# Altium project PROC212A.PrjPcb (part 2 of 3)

## Sheet PROC212A_ANALOG_JTAG_MUX, CAN & SOP_CTRL.SchDoc: JTAG_ANALOG_MUX, CAN & SOP_CTRL
size 431 x 279 mm; Date: Not shown in title block; ApprovedBy: Not shown in title block; CheckedBy: Not shown in title block; Author: Not shown in title block; CompanyName: Not shown in title block; DrawnBy: Mistral; Engineer: Not shown in title block; Organization: Not shown in title block; Address1: Not shown in title block; Address2: Not shown in title block; Address3: Not shown in title block; Address4: Not shown in title block; DocumentNumber: 9; Revision: Use project parameter SCH_Rev; SheetNumber: 9; SheetTotal: 15; PageSetup: Record=PageOptions¦CenterHorizontal=True¦CenterVertical=True¦PrintScale=1.00¦XCorrection=1.00¦YCorrection=1.00¦PrintKind=0¦BorderSize=5000000¦LeftOffset=0¦BottomOffset=0¦Orientation=2¦PaperLength=1000¦PaperWidth=1000¦Scale=100¦PaperSource=15¦PrintQuality=600¦MediaType=1¦DitherType=10¦PaperKind=Letter¦PrintScaleMode=1
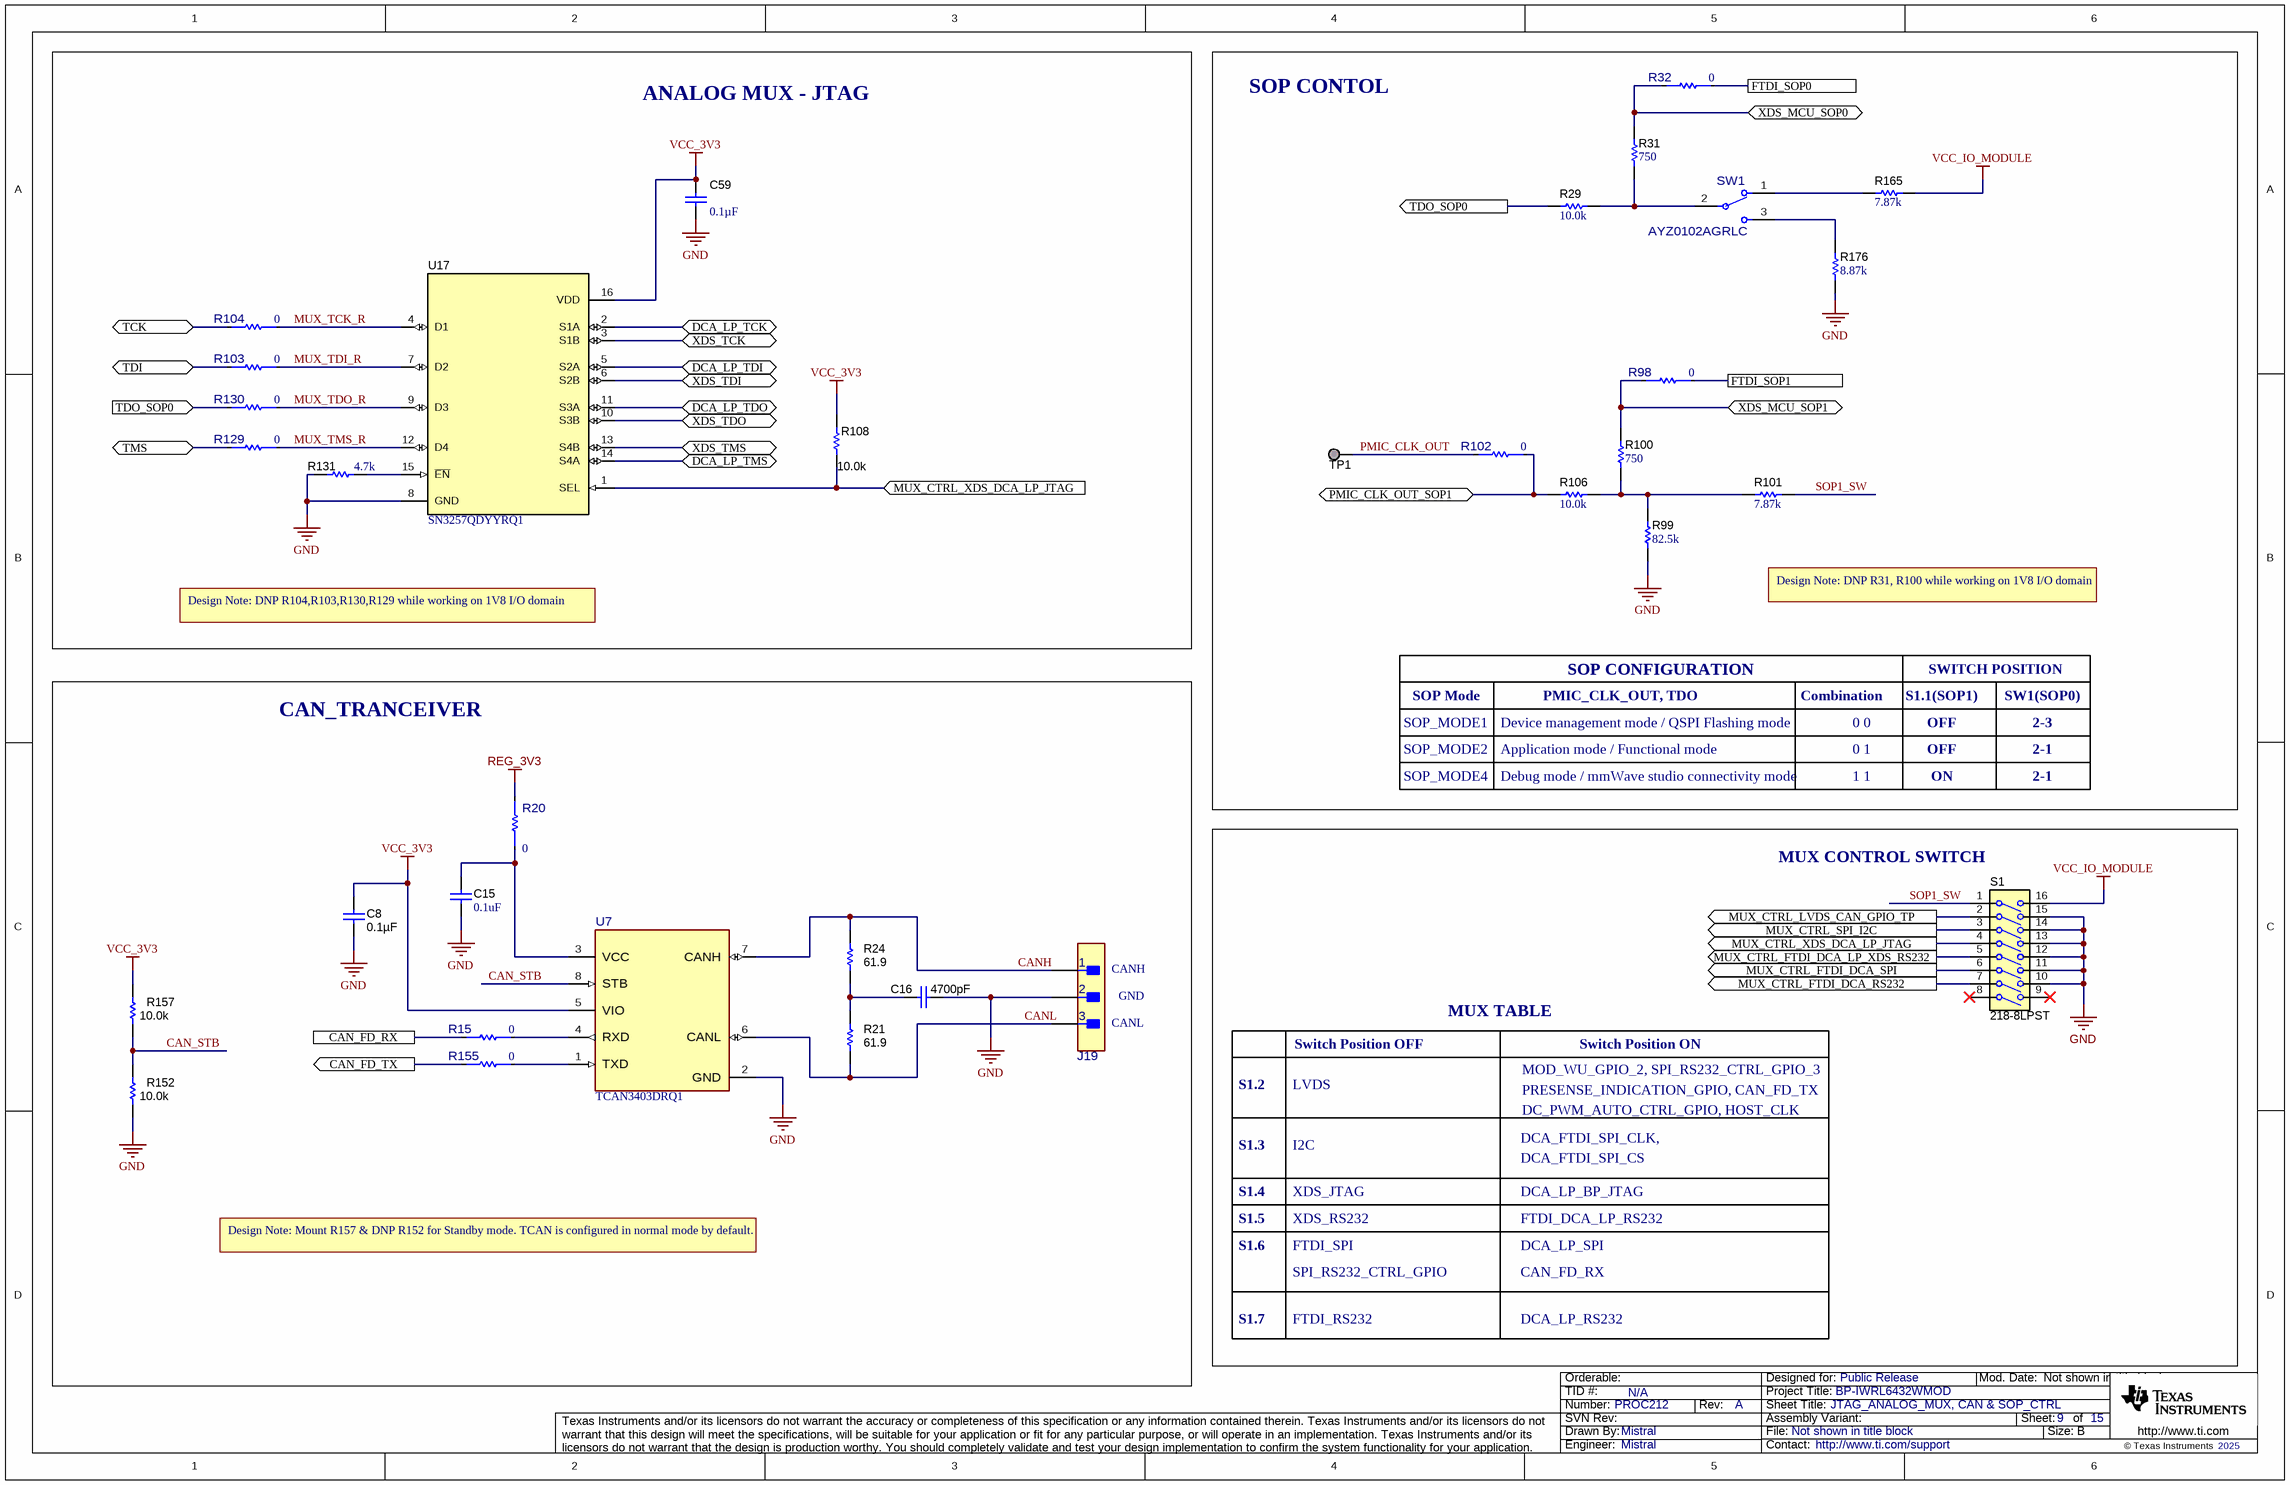
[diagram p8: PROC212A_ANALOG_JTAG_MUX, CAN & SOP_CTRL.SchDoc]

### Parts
C8  ValueDisplayed: 0.1µF  [0402L]  (hidden comment: C0402C104K8RACTU)
C15  ValueDisplayed: 0.1uF  [0402]  (hidden comment: GCM155R71H104KE02D)
C16  ValueDisplayed: 4700pF  [0402L]  (hidden comment: GCM155R71H472KA37D)
C59  ValueDisplayed: 0.1µF  [0402]  (hidden comment: C0402C104K8RACTU)
J19  M50-3930342  [FP-M50-3930342_HDR3-MFG]  (value not drawn)
R15  value 0  [FP-ERJ-2GE0R00X_0402-MFG]  (hidden comment: ERJ-2GE0R00X)
R20  value 0  [FP-ERJ-2GE0R00X_0402-MFG]  (hidden comment: ERJ-2GE0R00X)
R21  ValueDisplayed: 61.9  [0402L]  (hidden comment: CRCW040261R9FKED)
R24  ValueDisplayed: 61.9  [0402L]  (hidden comment: CRCW040261R9FKED)
R29  ValueDisplayed: 10.0k  [0402L]  (hidden comment: CRCW040210K0FKED)
R31  ValueDisplayed: 750  [0402L]  (hidden comment: CRCW0402750RFKED)
R32  value 0  [FP-ERJ-2GE0R00X_0402-MFG]  (hidden comment: ERJ-2GE0R00X)
R98  value 0  [FP-ERJ-2GE0R00X_0402-MFG]  (hidden comment: ERJ-2GE0R00X)
R99  ValueDisplayed: 82.5k  [0402L]  (hidden comment: CRCW040282K5FKED)
R100  ValueDisplayed: 750  [0402L]  (hidden comment: CRCW0402750RFKED)
R101  ValueDisplayed: 7.87k  [0402L]  (hidden comment: CRCW04027K87FKED)
R102  value 0  [FP-ERJ-2GE0R00X_0402-MFG]  (hidden comment: ERJ-2GE0R00X)
R103  value 0  [FP-ERJ-2GE0R00X_0402-MFG]  (hidden comment: ERJ-2GE0R00X)
R104  value 0  [FP-ERJ-2GE0R00X_0402-MFG]  (hidden comment: ERJ-2GE0R00X)
R106  ValueDisplayed: 10.0k  [0402L]  (hidden comment: CRCW040210K0FKED)
R108  ValueDisplayed: 10.0k  [0402L]  (hidden comment: CRCW040210K0FKED)
R129  value 0  [FP-ERJ-2GE0R00X_0402-MFG]  (hidden comment: ERJ-2GE0R00X)
R130  value 0  [FP-ERJ-2GE0R00X_0402-MFG]  (hidden comment: ERJ-2GE0R00X)
R131  ValueDisplayed: 4.7k  [0402]  (hidden comment: CRCW04024K70JNED)
R152  ValueDisplayed: 10.0k  [0402L]  (hidden comment: CRCW040210K0FKED)
R155  value 0  [FP-ERJ-2GE0R00X_0402-MFG]  (hidden comment: ERJ-2GE0R00X)
R157  ValueDisplayed: 10.0k  [0402L]  (hidden comment: CRCW040210K0FKED)
R165  ValueDisplayed: 7.87k  [0402L]  (hidden comment: CRCW04027K87FKED)
R176  ValueDisplayed: 8.87k  [0402]  (hidden comment: CRCW04028K87FKED)
S1  218-8LPST  [SW_218-8LP]
SW1  AYZ0102AGRLC  [FP-AYZ0102AGRLC_SMT_SW_7MM2_5MM3-MFG]
TP1  TESTPOINT  [TP_25MIL-SMT]  (value not drawn)  (no BOM)
U7  TCAN3403DRQ1  [D0008B-MFG]
U17  SN3257QDYYRQ1  [DYY0016A]

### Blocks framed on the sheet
ANALOG MUX - JTAG: C59 R103 R104 R108 R129-R131 U17
SOP CONTOL: R29 R31 R32 R98-R102 R106 R165 R176 SW1 TP1
CAN_TRANCEIVER: C8 C15 C16 J19 R15 R20 R21 R24 R152 R155 R157 U7

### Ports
CAN_FD_RX, CAN_FD_TX (out), DCA_LP_TCK (bidir), DCA_LP_TDI (bidir), DCA_LP_TDO (bidir), DCA_LP_TMS (bidir), FTDI_SOP0, FTDI_SOP1, MUX_CTRL_FTDI_DCA_LP_XDS_RS232 (out), MUX_CTRL_FTDI_DCA_RS232 (out), MUX_CTRL_FTDI_DCA_SPI (out), MUX_CTRL_LVDS_CAN_GPIO_TP (out), MUX_CTRL_SPI_I2C (out), MUX_CTRL_XDS_DCA_LP_JTAG (in), MUX_CTRL_XDS_DCA_LP_JTAG (out), PMIC_CLK_OUT_SOP1 (bidir), TCK (bidir), TDI (bidir), TDO_SOP0 (in), TDO_SOP0 (out), TMS (bidir), XDS_MCU_SOP0 (bidir), XDS_MCU_SOP1 (bidir), XDS_TCK (bidir), XDS_TDI (bidir), XDS_TDO (bidir), XDS_TMS (bidir)

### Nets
GND: C8.1 C15.1 C16.1 C59.2 J19.2 R99.1 R131.1 R152.1 R176.1 S1.10(7A) S1.11(6A) S1.12(5A) S1.13(4A) S1.14(3A) S1.15(2A) U7.2(GND) U17.8(GND)
REG_3V3: R20.2
VCC_3V3: C8.2 C59.1 R108.2 R157.2 U7.5(VIO) U17.16(VDD)
VCC_IO_MODULE: R165.2 S1.16(1A)
CAN_FD_RX: R15.2 ; port CAN_FD_RX
CAN_FD_TX: R155.2 ; port CAN_FD_TX
CAN_STB: R152.2 R157.1 U7.8(STB)
CANH: J19.1 R24.2 U7.7(CANH)
CANL: J19.3 R21.1 U7.6(CANL)
DCA_LP_TCK: U17.2(S1A) ; port DCA_LP_TCK
DCA_LP_TDI: U17.5(S2A) ; port DCA_LP_TDI
DCA_LP_TDO: U17.11(S3A) ; port DCA_LP_TDO
DCA_LP_TMS: U17.14(S4A) ; port DCA_LP_TMS
FTDI_SOP0: R32.1 ; port FTDI_SOP0
FTDI_SOP1: R98.1 ; port FTDI_SOP1
MUX_CTRL_FTDI_DCA_LP_XDS_RS232: S1.5 ; port MUX_CTRL_FTDI_DCA_LP_XDS_RS232
MUX_CTRL_FTDI_DCA_RS232: S1.7 ; port MUX_CTRL_FTDI_DCA_RS232
MUX_CTRL_FTDI_DCA_SPI: S1.6 ; port MUX_CTRL_FTDI_DCA_SPI
MUX_CTRL_LVDS_CAN_GPIO_TP: S1.2 ; port MUX_CTRL_LVDS_CAN_GPIO_TP
MUX_CTRL_SPI_I2C: S1.3 ; port MUX_CTRL_SPI_I2C
MUX_CTRL_XDS_DCA_LP_JTAG: R108.1 S1.4 U17.1(SEL) ; port MUX_CTRL_XDS_DCA_LP_JTAG
MUX_TCK_R: R104.1 U17.4(D1)
MUX_TDI_R: R103.1 U17.7(D2)
MUX_TDO_R: R130.1 U17.9(D3)
MUX_TMS_R: R129.1 U17.12(D4)
PMIC_CLK_OUT: R102.2 TP1.1
PMIC_CLK_OUT_SOP1: R102.1 R106.1 ; port PMIC_CLK_OUT_SOP1
SOP1_SW: R101.2 S1.1
TCK: R104.2 ; port TCK
TDI: R103.2 ; port TDI
TDO_SOP0: R29.1 R130.2 ; port TDO_SOP0
TMS: R129.2 ; port TMS
XDS_MCU_SOP0: R31.1 R32.2 ; port XDS_MCU_SOP0
XDS_MCU_SOP1: R98.2 R100.1 ; port XDS_MCU_SOP1
XDS_TCK: U17.3(S1B) ; port XDS_TCK
XDS_TDI: U17.6(S2B) ; port XDS_TDI
XDS_TDO: U17.10(S3B) ; port XDS_TDO
XDS_TMS: U17.13(S4B) ; port XDS_TMS
NetC15_2: C15.2 R20.1 U7.3(VCC)
NetC16_2: C16.2 R21.2 R24.1
NetR15_1: R15.1 U7.4(RXD)
NetR29_2: R29.2 R31.2 SW1.2(C)
NetR99_2: R99.2 R100.2 R101.1 R106.2
NetR131_2: R131.2 U17.15(~{EN})
NetR155_1: R155.1 U7.1(TXD)
NetR165_1: R165.1 SW1.1
NetR176_2: R176.2 SW1.3

Not connected (* = marked no-connect by the designer): S1 8* 9(8A)*

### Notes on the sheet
- Design Note: DNP R104,R103,R130,R129 while working on 1V8 I/O domain
- Design Note: DNP R31, R100 while working on 1V8 I/O domain
- SOP Mode
- PMIC_CLK_OUT, TDO
- SOP CONFIGURATION
- Combination
- S1.1(SOP1)
- SWITCH POSITION
- SW1(SOP0)
- SOP_MODE1
- SOP_MODE2
- Device management mode / QSPI Flashing mode
- Application mode / Functional mode
- 0 0
- 0 1
- OFF
- 2-1
- 2-3
- SOP_MODE4
- Debug mode / mmWave studio connectivity mode
- 1 1
- ON
- (near S1) MUX CONTROL SWITCH
- (near J19) CANH
- (near J19) CANL
- (near J19) GND
- MUX TABLE
- S1.2
- LVDS
- Switch Position OFF
- MOD_WU_GPIO_2, SPI_RS232_CTRL_GPIO_3
- PRESENSE_INDICATION_GPIO, CAN_FD_TX
- DC_PWM_AUTO_CTRL_GPIO, HOST_CLK
- Switch Position ON
- S1.3
- I2C
- DCA_FTDI_SPI_CLK,
- DCA_FTDI_SPI_CS
- Design Note: Mount R157 & DNP R152 for Standby mode. TCAN is configured in normal mode by default.
- S1.4
- S1.5
- S1.6
- XDS_RS232
- XDS_JTAG
- FTDI_SPI
- FTDI_DCA_LP_RS232
- DCA_LP_BP_JTAG
- DCA_LP_SPI
- SPI_RS232_CTRL_GPIO
- CAN_FD_RX
- S1.7
- FTDI_RS232
- DCA_LP_RS232

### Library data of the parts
C8 = CMP-0078241-1: CAP, CERM, 0.1 µF, 10 V,+/- 10%, X7R, 0402; Manufacturer: Kemet; TaMin_C: -55°C; Polarized: N; SizeAreaWB_mm2: 3; U/M: EA; Value: 0.1uF; TaMax_C: 125°C; SizeZ_mm: 0.6; SizeX_mm: 1; SizeY_mm: 0.5; Cap_Case: 0402; Value2: 10V; CompType: Capacitor; Cap_F: 100nF; AEC Category: Q200
C15 = CMP-0006356-2: CAP, CERM, 0.1 uF, 50 V, +/- 10%, X7R, AEC-Q200 Grade 1, 0402; Manufacturer: MuRata; TaMin_C: -55°C; Polarized: N; SizeAreaWB_mm2: 3; U/M: EA; Value: 0.1uF; TaMax_C: 125°C; SizeZ_mm: 0.6; SizeX_mm: 1; SizeY_mm: 0.5; Value2: 50V; AEC Qualified: Y; Cap_F: 100nF; AEC Category: Q200; Value1: Unknown
C16 = CMP-0006361-2: CAP, CERM, 4700 pF, 50 V, +/- 10%, X7R, AEC-Q200 Grade 1, 0402; Manufacturer: MuRata; TaMin_C: -55°C; Polarized: N; SizeAreaWB_mm2: 3; Value1: Unknown; U/M: EA; Value: 4700pF; TaMax_C: 125°C; SizeZ_mm: 0.6; SizeX_mm: 1; SizeY_mm: 0.5; Cap_Case: 0402; Value2: 50V; AEC Qualified: Y; Cap_F: 4.7nF; AEC Category: Q200
C59 = CMP-0078241-1: CAP, CERM, 0.1 µF, 10 V,+/- 10%, X7R, 0402; Manufacturer: Kemet; TaMin_C: -55°C; Polarized: N; SizeAreaWB_mm2: 3; U/M: EA; Value: 0.1uF; TaMax_C: 125°C; SizeZ_mm: 0.6; SizeX_mm: 1; SizeY_mm: 0.5; Value2: 10V; CompType: Capacitor; Cap_F: 100nF; AEC Category: Q200
J19 = CMP-0087785-1: CONN HEADER R/A 3POS 1.27MM; Manufacturer: Harwin; Row_Count: 1; Current_A: 1A; ContactFinish: Gold,Nickel
R15 R20 R32 R98 R102-R104 R129 R130 R155 = CMP-0002710-1: 0 Ohms Jumper Chip Resistor 0402 (1005 Metric) Automotive AEC-Q200 Thick Film; Manufacturer: Panasonic; SizeZ_mm: 0.4mm; AEC Qualified: Yes; AEC Grade: Grade 0; Power: 100mW
R21 R24 = CMP-0026491-2: RES, 61.9, 1%, 0.063 W, AEC-Q200 Grade 0, 0402; Manufacturer: Vishay-Dale; Power_W: 63mW; TempCo: 100 ppm/C; Value_Code: 61R9; Value: 61.9; EIA_Code: E96; SizeX_mm: 1; SizeY_mm: 0.5; SizeZ_mm: 0.6; Value2: 0.063W; AEC Qualified: Y; VDC_V: 50V; AEC Category: Q200; AEC Grade: 0
R29 R106 R108 R152 R157 = CMP-0025958-3: RES, 10.0 k, 1%, 0.063 W, AEC-Q200 Grade 0, 0402; Manufacturer: Vishay-Dale; Power_W: 63mW; TempCo: 100 ppm/C; Value_Code: 10k0; Value: 10.0k; EIA_Code: E96; Res_ohm: 10k; SizeX_mm: 1; SizeY_mm: 0.5; SizeZ_mm: 0.6; Value2: 0.063W; AEC Qualified: Y; VDC_V: 50V; AEC Category: Q200; AEC Grade: 0
R31 R100 = CMP-0026542-2: RES, 750, 1%, 0.063 W, AEC-Q200 Grade 0, 0402; Manufacturer: Vishay-Dale; Power_W: 63mW; TempCo: 100 ppm/C; Value_Code: 750R; Value: 750; EIA_Code: E96; SizeX_mm: 1; SizeY_mm: 0.5; SizeZ_mm: 0.6; Value2: 0.063W; AEC Qualified: Y; VDC_V: 50V; AEC Grade: 0; AEC Category: Q200
R99 = CMP-0026574-2: RES, 82.5 k, 1%, 0.063 W, AEC-Q200 Grade 0, 0402; Manufacturer: Vishay-Dale; Power_W: 63mW; TempCo: 100 ppm/C; Value_Code: 82k5; Value: 82.5k; EIA_Code: E96; SizeX_mm: 1; SizeY_mm: 0.5; SizeZ_mm: 0.6; Value2: 0.063W; AEC Qualified: Y; VDC_V: 50V; AEC Grade: 0; AEC Category: Q200
R101 R165 = CMP-0026557-2: RES, 7.87 k, 1%, 0.063 W, AEC-Q200 Grade 0, 0402; Manufacturer: Vishay-Dale; Power_W: 63mW; TempCo: 100 ppm/C; Value_Code: 7k87; Value: 7.87k; EIA_Code: E96; SizeX_mm: 1; SizeY_mm: 0.5; SizeZ_mm: 0.6; Value2: 0.063W; AEC Qualified: Y; VDC_V: 50V; AEC Grade: 0; AEC Category: Q200
R131 = CMP-0026938-5: RES, 4.7 k, 5%, 0.063 W, AEC-Q200 Grade 0, 0402; Manufacturer: Vishay-Dale; Power_W: 63mW; TempCo: 200 ppm/C; Value_Code: 4k70; Value: 4.7k; EIA_Code: E24; SizeX_mm: 1; SizeY_mm: 0.5; SizeZ_mm: 0.6; Value2: 0.063W; AEC Qualified: Y; VDC_V: 50V; AEC Category: Q200; AEC Grade: 0
R176 = CMP-0026592-2: RES, 8.87 k, 1%, 0.063 W, AEC-Q200 Grade 0, 0402; Manufacturer: Vishay-Dale; Power_W: 63mW; TempCo: 100 ppm/C; Value_Code: 8k87; Value: 8.87k; EIA_Code: E96; SizeX_mm: 1; SizeY_mm: 0.5; SizeZ_mm: 0.6; Value2: 0.063W; AEC Qualified: Y; VDC_V: 50V; AEC Category: Q200; AEC Grade: 0
S1 = CMP-0002229-1: Switch, SPST, 8 Pos, 25mA, 24VDC, SMD; Manufacturer: CTS Electrocomponents; CurrentRating_mA: 25A; PositionCount: 8; VDC_V: 24V; SwitchFunction: Off-On
SW1 = CMP-0096333-1: Slide Switch SPDT Surface Mount, Right Angle; Manufacturer: C&K Switches; Coil Resistance_ohm: 80mΩ; SizeZ_mm: 1.5mm; AEC Qualified: No; VDC_V: 12V; Contact Current Rating: 100mA; Electromechanical Life: 10000Cycles
TP1 = CMP-0078143-3: TEST POINT.  No entry in BOM.
U7 = CMP-0121020-1: Dual, Simultaneous-Sampling, 16-Bit, 5 MSPS SAR ADCs; Manufacturer: Texas Instruments; SizeZ_mm: 1.75mm; AEC Qualified: Yes; AEC Grade: Grade 1; Interface: CAN; Max Supply Voltage: 3.6V; Min Supply Voltage: 1.7V; Standoff Height: 0.11mm
U17 = CMP-0860151-2: SN3257QDYYRQ1, DYY0016A (SOT-23-THIN-16); Manufacturer: Texas Instruments; SizeX_mm: 3.26; SizeArea_mm2: 13.692; SizeAreaWB_mm2: 22.152; AEC Qualified: Y; CompType: IC; SizeZ_mm: 1.1; AEC Category: Q200; SizeY_mm: 4.2

## Sheet PROC212A_Current_sensors_EPROM.SchDoc: CURRENT_SENSORS_EEPROM
size 431 x 279 mm; Date: Not shown in title block; ApprovedBy: Not shown in title block; CheckedBy: Not shown in title block; Author: Not shown in title block; CompanyName: Not shown in title block; DrawnBy: Mistral; Engineer: Not shown in title block; Organization: Not shown in title block; Address1: Not shown in title block; Address2: Not shown in title block; Address3: Not shown in title block; Address4: Not shown in title block; DocumentNumber: 10; Revision: Use project parameter SCH_Rev; SheetNumber: 10; SheetTotal: 15; PageSetup: Record=PageOptions¦CenterHorizontal=True¦CenterVertical=True¦PrintScale=1.00¦XCorrection=1.00¦YCorrection=1.00¦PrintKind=0¦BorderSize=5000000¦LeftOffset=0¦BottomOffset=0¦Orientation=2¦PaperLength=1000¦PaperWidth=1000¦Scale=100¦PaperSource=15¦PrintQuality=600¦MediaType=1¦DitherType=10¦PaperKind=Letter¦PrintScaleMode=1
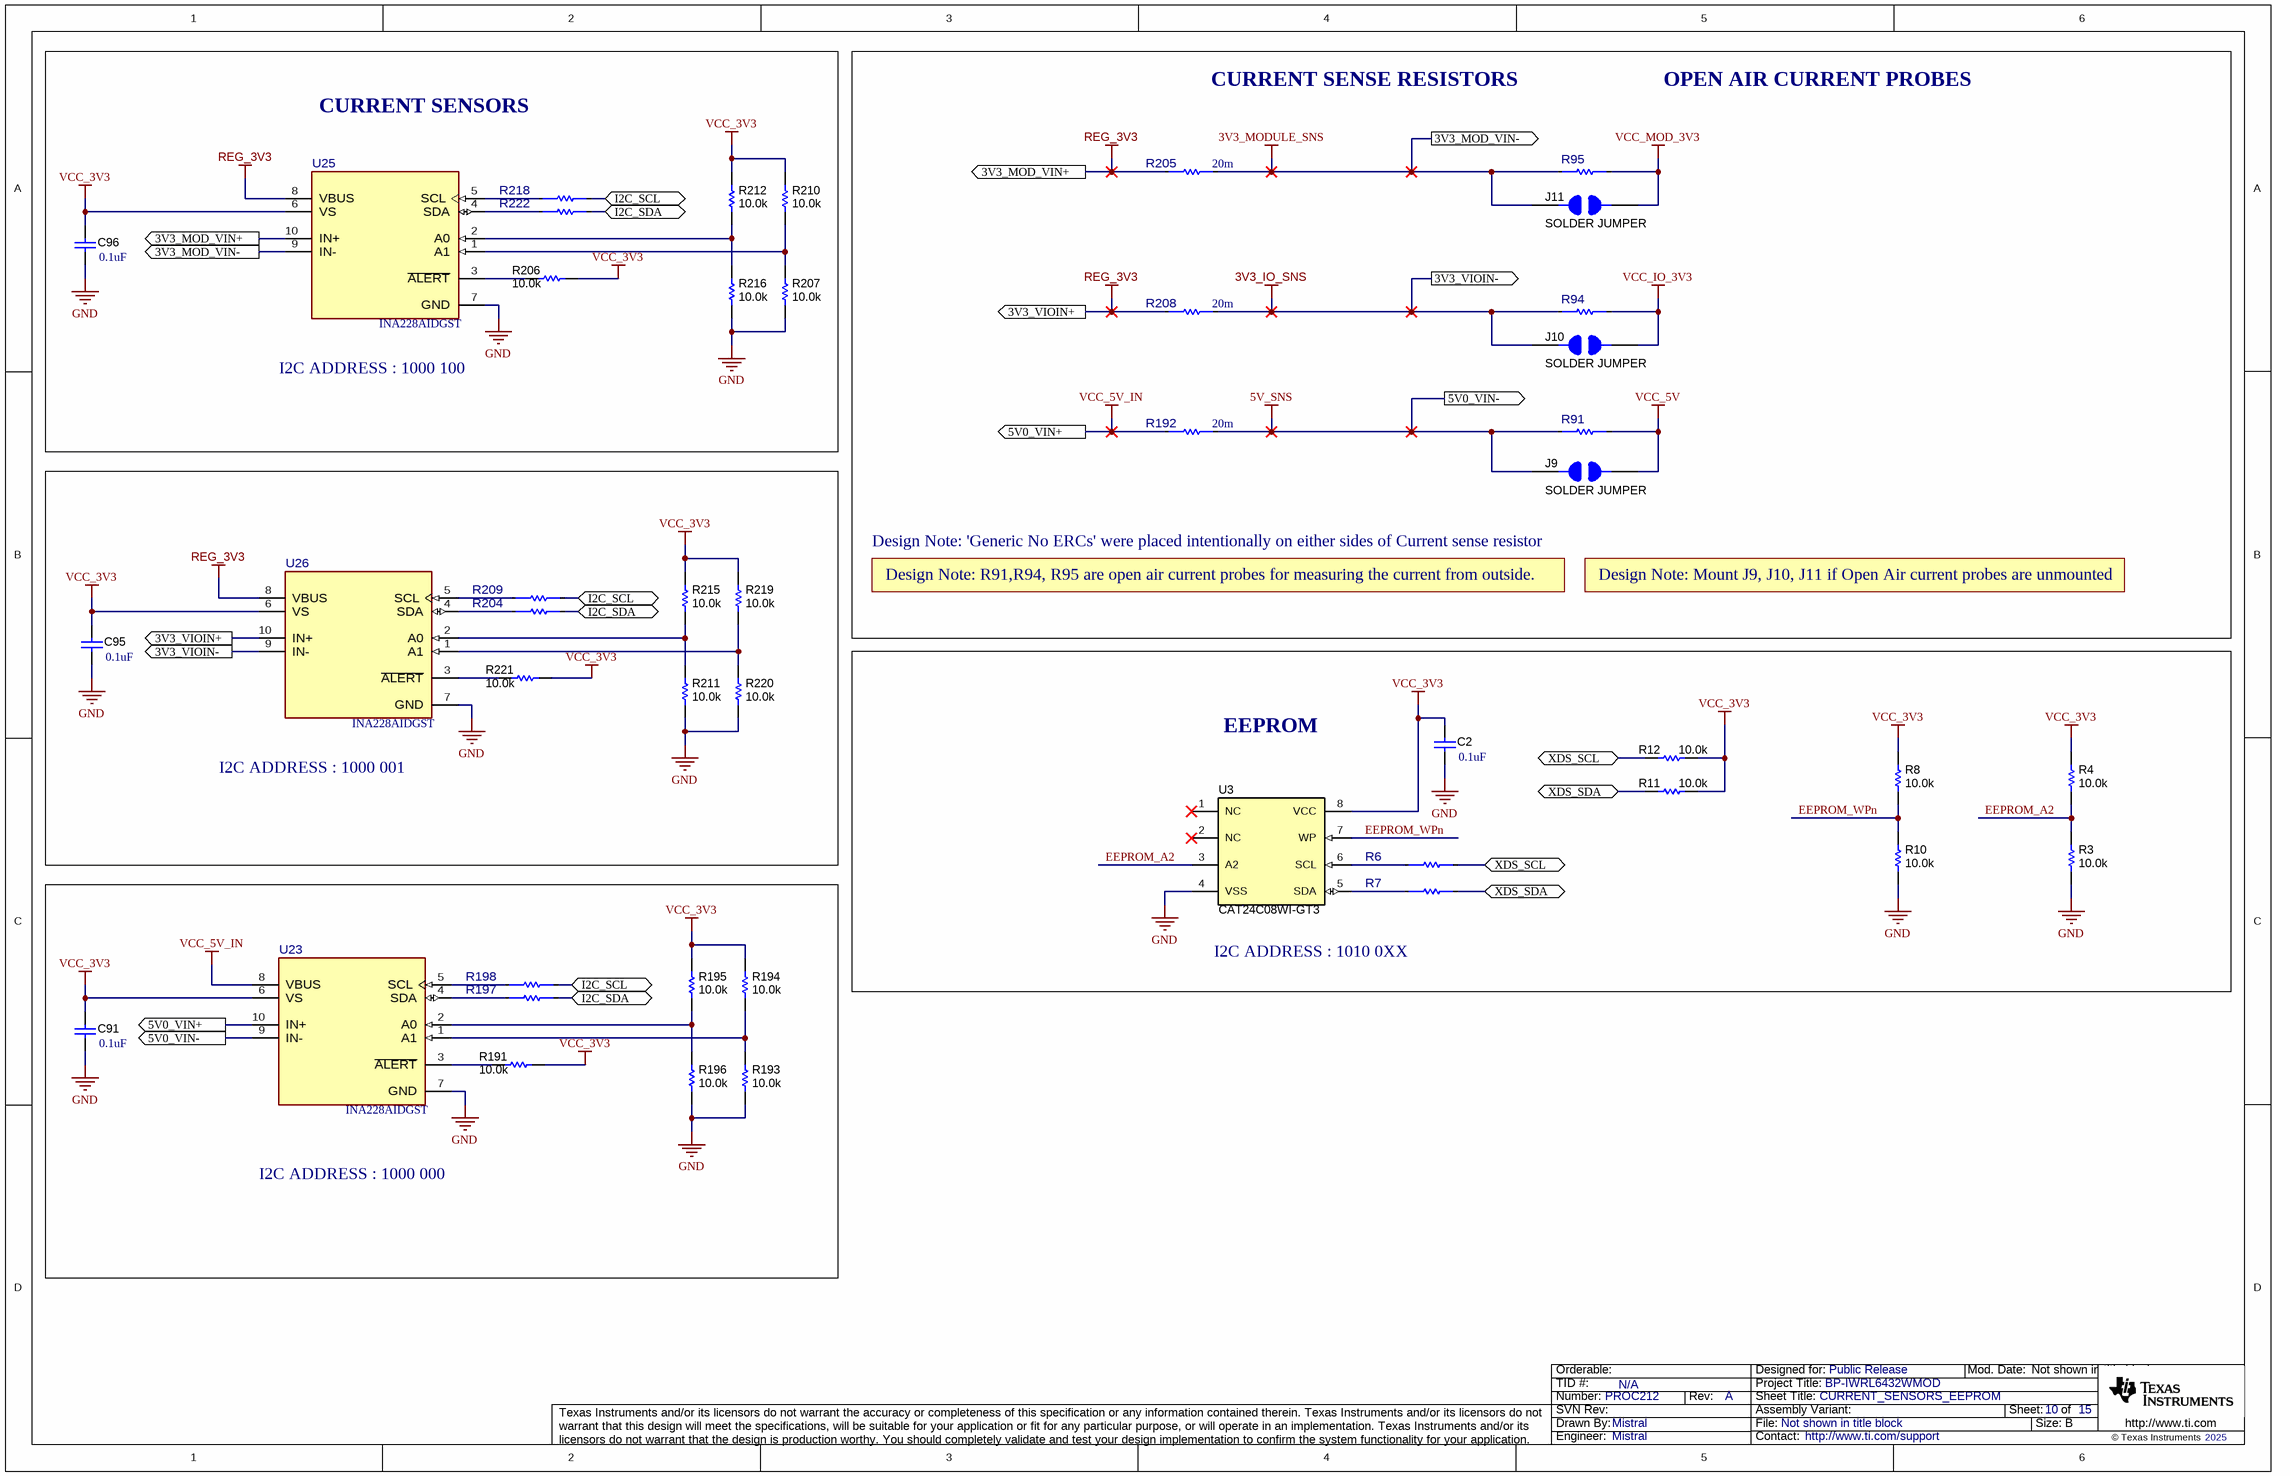
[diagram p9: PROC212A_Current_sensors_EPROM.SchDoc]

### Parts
C2  ValueDisplayed: 0.1uF  [0402]  (hidden comment: GCM155R71H104KE02D)
C91  ValueDisplayed: 0.1uF  [0402]  (hidden comment: GCM155R71H104KE02D)
C95  ValueDisplayed: 0.1uF  [0402]  (hidden comment: GCM155R71H104KE02D)
C96  ValueDisplayed: 0.1uF  [0402]  (hidden comment: GCM155R71H104KE02D)
J9  SOLDER JUMPER  [SolderJumper]
J10  SOLDER JUMPER  [SolderJumper]
J11  SOLDER JUMPER  [SolderJumper]
R3  ValueDisplayed: 10.0k  [0402L]  (hidden comment: CRCW040210K0FKED)
R4  ValueDisplayed: 10.0k  [0402L]  (hidden comment: CRCW040210K0FKED)
R6  ERJ-2GE0R00X  [FP-ERJ-2GE0R00X_0402-MFG]  (value not drawn)
R7  ERJ-2GE0R00X  [FP-ERJ-2GE0R00X_0402-MFG]  (value not drawn)
R8  ValueDisplayed: 10.0k  [0402L]  (hidden comment: CRCW040210K0FKED)
R10  ValueDisplayed: 10.0k  [0402L]  (hidden comment: CRCW040210K0FKED)
R11  ValueDisplayed: 10.0k  [0402L]  (hidden comment: CRCW040210K0FKED)
R12  ValueDisplayed: 10.0k  [0402L]  (hidden comment: CRCW040210K0FKED)
R91  OAR3R010FLF  [FP-OAR3R010FLF_RADIAL-MFG]  (value not drawn)
R94  OAR3R010FLF  [FP-OAR3R010FLF_RADIAL-MFG]  (value not drawn)
R95  OAR3R010FLF  [FP-OAR3R010FLF_RADIAL-MFG]  (value not drawn)
R191  ValueDisplayed: 10.0k  [0402L]  (hidden comment: CRCW040210K0FKED)
R192  value 20m  [FP-WSL1206R0200FEB_1206-MFG]  (hidden comment: WSL1206R0200FEB)
R193  ValueDisplayed: 10.0k  [0402L]  (hidden comment: CRCW040210K0FKED)
R194  ValueDisplayed: 10.0k  [0402L]  (hidden comment: CRCW040210K0FKED)
R195  ValueDisplayed: 10.0k  [0402L]  (hidden comment: CRCW040210K0FKED)
R196  ValueDisplayed: 10.0k  [0402L]  (hidden comment: CRCW040210K0FKED)
R197  ERJ-2GE0R00X  [FP-ERJ-2GE0R00X_0402-MFG]  (value not drawn)
R198  ERJ-2GE0R00X  [FP-ERJ-2GE0R00X_0402-MFG]  (value not drawn)
R204  ERJ-2GE0R00X  [FP-ERJ-2GE0R00X_0402-MFG]  (value not drawn)
R205  value 20m  [FP-WSL1206R0200FEB_1206-MFG]  (hidden comment: WSL1206R0200FEB)
R206  ValueDisplayed: 10.0k  [0402L]  (hidden comment: CRCW040210K0FKED)
R207  ValueDisplayed: 10.0k  [0402L]  (hidden comment: CRCW040210K0FKED)
R208  value 20m  [FP-WSL1206R0200FEB_1206-MFG]  (hidden comment: WSL1206R0200FEB)
R209  ERJ-2GE0R00X  [FP-ERJ-2GE0R00X_0402-MFG]  (value not drawn)
R210  ValueDisplayed: 10.0k  [0402L]  (hidden comment: CRCW040210K0FKED)
R211  ValueDisplayed: 10.0k  [0402L]  (hidden comment: CRCW040210K0FKED)
R212  ValueDisplayed: 10.0k  [0402L]  (hidden comment: CRCW040210K0FKED)
R215  ValueDisplayed: 10.0k  [0402L]  (hidden comment: CRCW040210K0FKED)
R216  ValueDisplayed: 10.0k  [0402L]  (hidden comment: CRCW040210K0FKED)
R218  ERJ-2GE0R00X  [FP-ERJ-2GE0R00X_0402-MFG]  (value not drawn)
R219  ValueDisplayed: 10.0k  [0402L]  (hidden comment: CRCW040210K0FKED)
R220  ValueDisplayed: 10.0k  [0402L]  (hidden comment: CRCW040210K0FKED)
R221  ValueDisplayed: 10.0k  [0402L]  (hidden comment: CRCW040210K0FKED)
R222  ERJ-2GE0R00X  [FP-ERJ-2GE0R00X_0402-MFG]  (value not drawn)
U3  CAT24C08WI-GT3  [SOIC-8]
U23  INA228AIDGST  [DGS0010A-MFG]
U25  INA228AIDGST  [DGS0010A-MFG]
U26  INA228AIDGST  [DGS0010A-MFG]

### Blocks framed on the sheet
CURRENT SENSORS: C96 R206 R207 R210 R212 R216 R218 R222 U25
I2C ADDRESS : 1000 001: C95 R204 R209 R211 R215 R219-R221 U26
EEPROM: C2 R3 R4 R6-R8 R10-R12 U3
I2C ADDRESS : 1000 000: C91 R191 R193-R198 U23

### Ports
3V3_MOD_VIN+ (out), 3V3_MOD_VIN- (out), 3V3_VIOIN+ (out), 3V3_VIOIN- (out), 5V0_VIN+ (out), 5V0_VIN- (out), I2C_SCL (bidir), I2C_SDA (bidir), XDS_SCL (bidir), XDS_SDA (bidir)

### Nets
3V3_IO_SNS: J10.1 R94.1 R208.2 U26.9(IN-) ; port 3V3_VIOIN-
3V3_MODULE_SNS: J11.1 R95.1 R205.2 U25.9(IN-) ; port 3V3_MOD_VIN-
5V_SNS: J9.1 R91.1 R192.2 U23.9(IN-) ; port 5V0_VIN-
GND: C2.2 C91.2 C95.2 C96.2 R3.1 R10.1 R193.1 R196.1 R207.1 R211.1 R216.1 R220.1 U3.4(VSS) U23.7(GND) U25.7(GND) U26.7(GND)
REG_3V3: R205.1 R208.1 U25.8(VBUS) U25.10(IN+) U26.8(VBUS) U26.10(IN+) ; port 3V3_MOD_VIN+, port 3V3_VIOIN+
VCC_3V3: C2.1 C91.1 C95.1 C96.1 R4.2 R8.2 R11.1 R12.1 R191.1 R194.2 R195.2 R206.1 R210.2 R212.2 R215.2 R219.2 R221.1 U3.8(VCC) U23.6(VS) U25.6(VS) U26.6(VS)
VCC_5V: J9.2 R91.2
VCC_5V_IN: R192.1 U23.8(VBUS) U23.10(IN+) ; port 5V0_VIN+
VCC_IO_3V3: J10.2 R94.2
VCC_MOD_3V3: J11.2 R95.2
EEPROM_A2: R3.2 R4.1 U3.3(A2)
EEPROM_WPn: R8.1 R10.2 U3.7(WP)
I2C_SCL: R198.2 R209.2 R218.2 ; port I2C_SCL
I2C_SDA: R197.2 R204.2 R222.2 ; port I2C_SDA
XDS_SCL: R6.2 R12.2 ; port XDS_SCL
XDS_SDA: R7.2 R11.2 ; port XDS_SDA
NetR6_1: R6.1 U3.6(SCL)
NetR7_1: R7.1 U3.5(SDA)
NetR191_2: R191.2 U23.3(~{ALERT})
NetR193_2: R193.2 R194.1 U23.1(A1)
NetR195_1: R195.1 R196.2 U23.2(A0)
NetR197_1: R197.1 U23.4(SDA)
NetR198_1: R198.1 U23.5(SCL)
NetR204_1: R204.1 U26.4(SDA)
NetR206_2: R206.2 U25.3(~{ALERT})
NetR207_2: R207.2 R210.1 U25.1(A1)
NetR209_1: R209.1 U26.5(SCL)
NetR211_2: R211.2 R215.1 U26.2(A0)
NetR212_1: R212.1 R216.2 U25.2(A0)
NetR218_1: R218.1 U25.5(SCL)
NetR219_1: R219.1 R220.2 U26.1(A1)
NetR221_2: R221.2 U26.3(~{ALERT})
NetR222_1: R222.1 U25.4(SDA)

Not connected (* = marked no-connect by the designer): U3 1(NC)* 2(NC)*

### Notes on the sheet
- CURRENT SENSE RESISTORS
- OPEN AIR CURRENT PROBES
- I2C ADDRESS : 1000 100
- Design Note: 'Generic No ERCs' were placed intentionally on either sides of Current sense resistor
- Design Note: R91,R94, R95 are open air current probes for measuring the current from outside.
- Design Note: Mount J9, J10, J11 if Open Air current probes are unmounted
- I2C ADDRESS : 1010 0XX

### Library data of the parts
C2 C91 C95 C96 = CMP-0006356-2: CAP, CERM, 0.1 uF, 50 V, +/- 10%, X7R, AEC-Q200 Grade 1, 0402; Manufacturer: MuRata; TaMin_C: -55°C; Polarized: N; SizeAreaWB_mm2: 3; Value1: Unknown; U/M: EA; Value: 0.1uF; TaMax_C: 125°C; SizeZ_mm: 0.6; SizeX_mm: 1; SizeY_mm: 0.5; Value2: 50V; AEC Qualified: Y; Cap_F: 100nF; AEC Category: Q200
J9-J11 = CMP-0080367-2: Solder Jumper, SMT; Manufacturer: NA
R3 R4 R8 R10-R12 R191 R193-R196 R206 R207 R210-R212 R215 R216 R219-R221 = CMP-0025958-3: as R29 on sheet PROC212A_ANALOG_JTAG_MUX, CAN & SOP_CTRL
R6 R7 R197 R198 R204 R209 R218 R222 = CMP-0002710-1: 0 Ohms Jumper Chip Resistor 0402 (1005 Metric) Automotive AEC-Q200 Thick Film; Manufacturer: Panasonic; Value: 0; SizeZ_mm: 0.4mm; AEC Qualified: Yes; AEC Grade: Grade 0; Power: 100mW
R91 R94 R95 = CMP-0125889-2: 10 mOhms ±1% 3W Through Hole Resistor Radial Current Sense, Flame Proof, Pulse Withstanding, Safety Metal Element; Manufacturer: TT Electronics/IRC; AEC Qualified: No; Res_ohm: 10m; TempCo: 20ppm/°C; SizeZ_mm: 12mm; Value: 10m
R192 R205 R208 = CMP-0098430-1: Res Metal Strip 1206 0.02 Ohm 1% 1/4W ±75ppm/°C Molded SMD SMD T/R; Manufacturer: Vishay Dale; AEC Grade: Grade 0; AEC Qualified: Yes; Power_W: 250mW; SizeZ_mm: 0.889mm; Category 5C6A91606D4187Ad: Resistors; Category 7542B8484461Ae85: Passive Components; Category Cd01000Bfc2916C6: Single Components
U3 = CMP-0005309-2: IC, EEPROM, 8KBIT, 400KHZ, 8SOIC; Manufacturer: ON Semiconductor; SizeAreaWB_mm2: 55.131; SizeZ_mm: 1.75; SizeX_mm: 5.99; SizeY_mm: 4.9; SizeArea_mm2: 29.351
U23 U25 U26 = CMP-0098432-1: Current Sense Amplifier 1 Circuit 10-VSSOP; Manufacturer: Texas Instruments; SizeZ_mm: 1.1mm; AEC Qualified: No; Input Bias Current: 0.01uA; Input Offset Voltage: 1mV; Max Supply Voltage: 5.5V; Min Supply Voltage: 2.7V; Nominal Supply Current: 640uA; Number Of Channels: 1; Standoff Height: 0.05mm; TaMax_C: +125°C; TaMin_C: -40°C; TJmax_C: +150°C

## Sheet PROC212A_XDS110_Interface.SchDoc: XDS110_INTERFACE
size 431 x 279 mm; Date: Not shown in title block; ApprovedBy: Not shown in title block; CheckedBy: Not shown in title block; Author: Not shown in title block; CompanyName: Not shown in title block; DrawnBy: Mistral; Engineer: Not shown in title block; Organization: Not shown in title block; Address1: Not shown in title block; Address2: Not shown in title block; Address3: Not shown in title block; Address4: Not shown in title block; DocumentNumber: 11; Revision: Use project parameter SCH_Rev; SheetNumber: 11; SheetTotal: 15; PageSetup: Record=PageOptions¦CenterHorizontal=True¦CenterVertical=True¦PrintScale=1.00¦XCorrection=1.00¦YCorrection=1.00¦PrintKind=0¦BorderSize=5000000¦LeftOffset=0¦BottomOffset=0¦Orientation=2¦PaperLength=1000¦PaperWidth=1000¦Scale=100¦PaperSource=15¦PrintQuality=600¦MediaType=1¦DitherType=10¦PaperKind=Letter¦PrintScaleMode=1
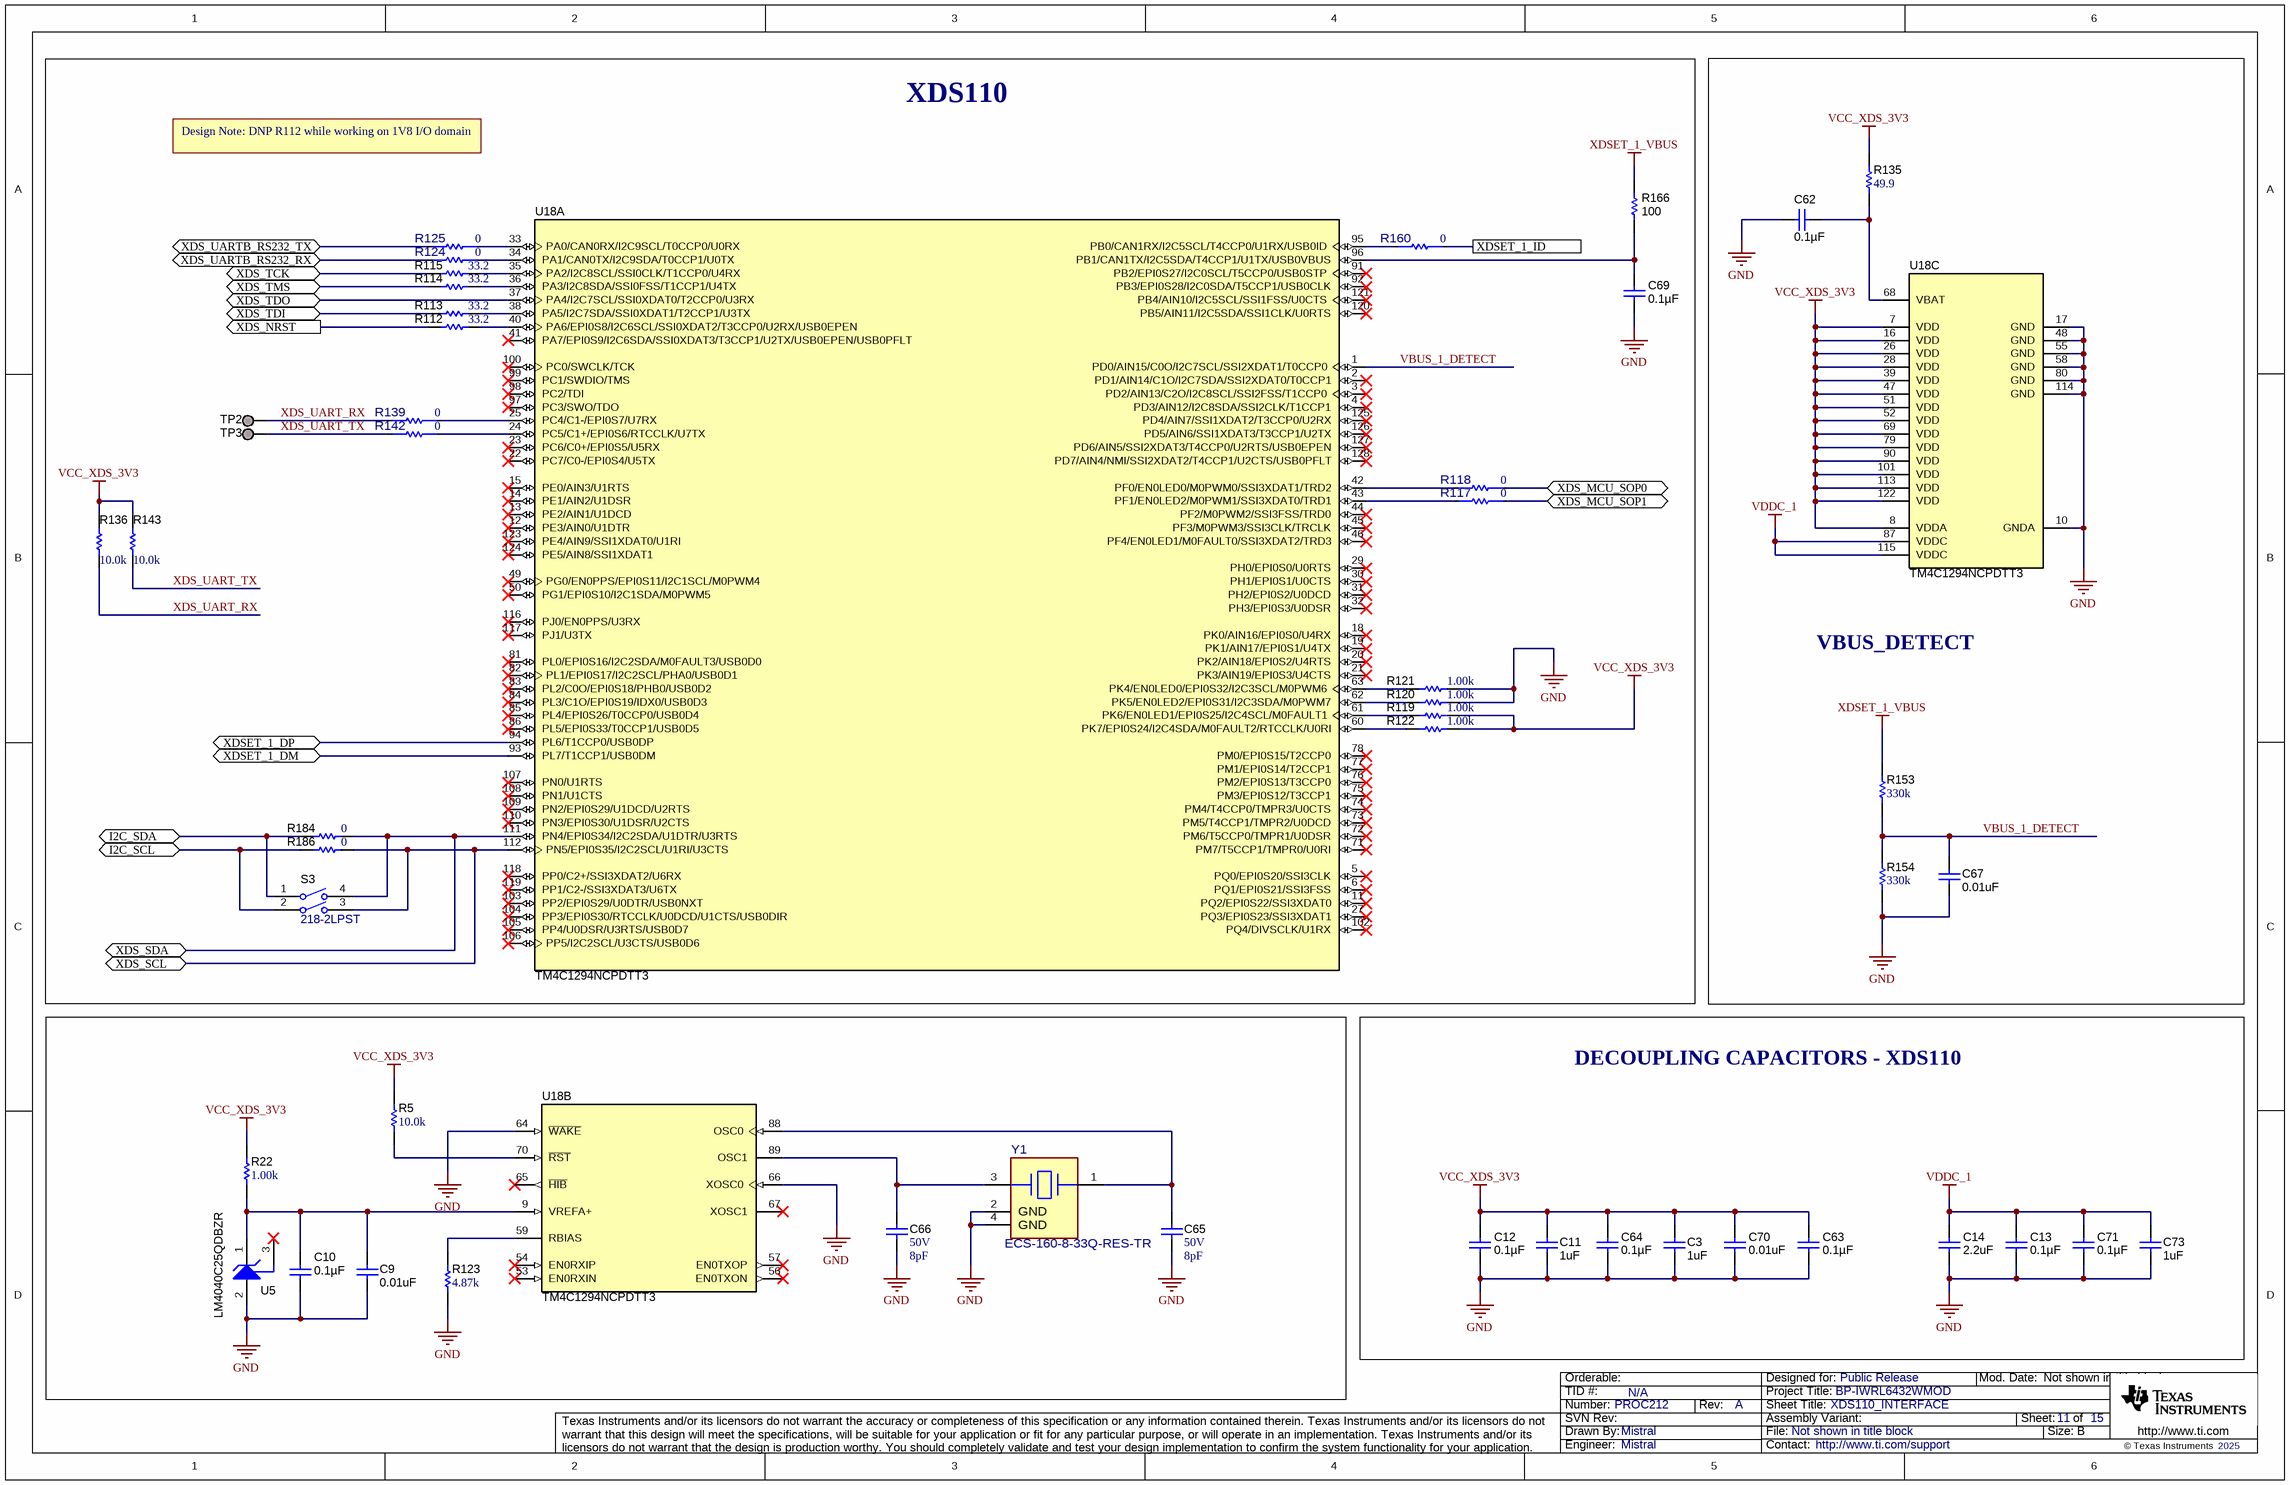
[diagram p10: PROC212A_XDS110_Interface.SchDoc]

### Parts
C3  ValueDisplayed: 1uF  [0402L]  (hidden comment: GRT155C81A105KE01D)
C9  ValueDisplayed: 0.01uF  [0402L]  (hidden comment: GCM155R71E103KA37D)
C10  ValueDisplayed: 0.1µF  [0402L]  (hidden comment: C0402C104K8RACTU)
C11  ValueDisplayed: 1uF  [0402L]  (hidden comment: GRT155C81A105KE01D)
C12  ValueDisplayed: 0.1µF  [0402L]  (hidden comment: C0402C104K8RACTU)
C13  ValueDisplayed: 0.1µF  [0402L]  (hidden comment: C0402C104K8RACTU)
C14  ValueDisplayed: 2.2uF  [0402_065L]  (hidden comment: C1005X7S1A225K050BC)
C62  ValueDisplayed: 0.1µF  [0402L]  (hidden comment: C0402C104K8RACTU)
C63  ValueDisplayed: 0.1µF  [0402L]  (hidden comment: C0402C104K8RACTU)
C64  ValueDisplayed: 0.1µF  [0402L]  (hidden comment: C0402C104K8RACTU)
C65  VDC_V: 50V  ValueDisplayed: 8pF  [0402L]  (hidden comment: CC0402DRNPO9BN8R0)
C66  VDC_V: 50V  ValueDisplayed: 8pF  [0402L]  (hidden comment: CC0402DRNPO9BN8R0)
C67  ValueDisplayed: 0.01uF  [0402L]  (hidden comment: GCM155R71E103KA37D)
C69  ValueDisplayed: 0.1µF  [0402L]  (hidden comment: C0402C104K8RACTU)
C70  ValueDisplayed: 0.01uF  [0402L]  (hidden comment: GCM155R71E103KA37D)
C71  ValueDisplayed: 0.1µF  [0402L]  (hidden comment: C0402C104K8RACTU)
C73  ValueDisplayed: 1uF  [0402L]  (hidden comment: GRT155C81A105KE01D)
R5  ValueDisplayed: 10.0k  [0402L]  (hidden comment: CRCW040210K0FKED)
R22  ValueDisplayed: 1.00k  [0402L]  (hidden comment: CRCW04021K00FKED)
R112  ValueDisplayed: 33.2  [0402]  (hidden comment: CRCW040233R2FKED)
R113  ValueDisplayed: 33.2  [0402]  (hidden comment: CRCW040233R2FKED)
R114  ValueDisplayed: 33.2  [0402]  (hidden comment: CRCW040233R2FKED)
R115  ValueDisplayed: 33.2  [0402]  (hidden comment: CRCW040233R2FKED)
R117  value 0  [FP-ERJ-2GE0R00X_0402-MFG]  (hidden comment: ERJ-2GE0R00X)
R118  value 0  [FP-ERJ-2GE0R00X_0402-MFG]  (hidden comment: ERJ-2GE0R00X)
R119  ValueDisplayed: 1.00k  [0402L]  (hidden comment: CRCW04021K00FKED)
R120  ValueDisplayed: 1.00k  [0402L]  (hidden comment: CRCW04021K00FKED)
R121  ValueDisplayed: 1.00k  [0402L]  (hidden comment: CRCW04021K00FKED)
R122  ValueDisplayed: 1.00k  [0402L]  (hidden comment: CRCW04021K00FKED)
R123  ValueDisplayed: 4.87k  [0402L]  (hidden comment: CRCW04024K87FKED)
R124  value 0  [FP-ERJ-2GE0R00X_0402-MFG]  (hidden comment: ERJ-2GE0R00X)
R125  value 0  [FP-ERJ-2GE0R00X_0402-MFG]  (hidden comment: ERJ-2GE0R00X)
R135  ValueDisplayed: 49.9  [0402L]  (hidden comment: CRCW040249R9FKED)
R136  ValueDisplayed: 10.0k  [0402L]  (hidden comment: CRCW040210K0FKED)
R139  value 0  [FP-ERJ-2GE0R00X_0402-MFG]  (hidden comment: ERJ-2GE0R00X)
R142  value 0  [FP-ERJ-2GE0R00X_0402-MFG]  (hidden comment: ERJ-2GE0R00X)
R143  ValueDisplayed: 10.0k  [0402L]  (hidden comment: CRCW040210K0FKED)
R153  ValueDisplayed: 330k  [0402L]  (hidden comment: CRCW0402330KFKED)
R154  ValueDisplayed: 330k  [0402L]  (hidden comment: CRCW0402330KFKED)
R160  value 0  [FP-ERJ-2GE0R00X_0402-MFG]  (hidden comment: ERJ-2GE0R00X)
R166  ValueDisplayed: 100  [0402L]  (hidden comment: ERJ-2GEJ101X)
R184  ValueDisplayed: 0  [0402]  (hidden comment: ERJ-2GE0R00X)
R186  ValueDisplayed: 0  [0402]  (hidden comment: ERJ-2GE0R00X)
S3  218-2LPST  [SW_218-2LP]
TP2  TESTPOINT  [TP_25MIL-SMT]  (value not drawn)  (no BOM)
TP3  TESTPOINT  [TP_25MIL-SMT]  (value not drawn)  (no BOM)
U5  LM4040C25QDBZR  [DBZ0003A_N]
U18  TM4C1294NCPDTT3  [PDT0128A]  (parts A,B,C of 3)
Y1  ECS-160-8-33Q-RES-TR  [FP-ECS-160-8-33Q-RES-TR_SMT4_3MM2_2MM5-MFG]

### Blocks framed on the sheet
VBUS_DETECT: C62 C67 R135 R153 R154 U18
DECOUPLING CAPACITORS - XDS110: C3 C11-C14 C63 C64 C70 C71 C73

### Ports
I2C_SCL (bidir), I2C_SDA (bidir), XDS_MCU_SOP0 (bidir), XDS_MCU_SOP1 (bidir), XDS_NRST (out), XDS_SCL (bidir), XDS_SDA (bidir), XDS_TCK (bidir), XDS_TDI (bidir), XDS_TDO (bidir), XDS_TMS (bidir), XDS_UARTB_RS232_RX (bidir), XDS_UARTB_RS232_TX (bidir), XDSET_1_DM (bidir), XDSET_1_DP (bidir), XDSET_1_ID

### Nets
GND: C3.2 C9.1 C10.1 C11.2 C12.1 C13.1 C14.1 C62.1 C63.1 C64.1 C65.1 C66.1 C67.1 C69.2 C70.2 C71.1 C73.2 R120.2 R121.2 R123.1 R154.1 U5.2(ANODE) U18.10(GNDA) U18.17(GND) U18.48(GND) U18.55(GND) U18.58(GND) U18.64(~{WAKE}) U18.66(XOSC0) U18.80(GND) U18.114(GND) Y1.2(GND) Y1.4(GND)
VCC_XDS_3V3: C3.1 C11.1 C12.2 C63.2 C64.2 C70.1 R5.2 R22.2 R119.2 R122.2 R135.1 R136.2 R143.1 U18.7(VDD) U18.8(VDDA) U18.16(VDD) U18.26(VDD) U18.28(VDD) U18.39(VDD) U18.47(VDD) U18.51(VDD) U18.52(VDD) U18.69(VDD) U18.79(VDD) U18.90(VDD) U18.101(VDD) U18.113(VDD) U18.122(VDD)
VDDC_1: C13.2 C14.2 C71.2 C73.1 U18.87(VDDC) U18.115(VDDC)
XDSET_1_VBUS: R153.2 R166.2
I2C_SCL: R186.1 S3.2 ; port I2C_SCL
I2C_SDA: R184.1 S3.1 ; port I2C_SDA
VBUS_1_DETECT: C67.2 R153.1 R154.2 U18.1(PD0/AIN15/C0O/I2C7SCL/SSI2XDAT1/T0CCP0)
XDS_MCU_SOP0: R118.1 ; port XDS_MCU_SOP0
XDS_MCU_SOP1: R117.1 ; port XDS_MCU_SOP1
XDS_NRST: R112.2 ; port XDS_NRST
XDS_SCL: R186.2 S3.3 U18.112(PN5/EPI0S35/I2C2SCL/U1RI/U3CTS) ; port XDS_SCL
XDS_SDA: R184.2 S3.4 U18.111(PN4/EPI0S34/I2C2SDA/U1DTR/U3RTS) ; port XDS_SDA
XDS_TCK: R115.2 ; port XDS_TCK
XDS_TDI: R113.2 ; port XDS_TDI
XDS_TDO: U18.37(PA4/I2C7SCL/SSI0XDAT0/T2CCP0/U3RX) ; port XDS_TDO
XDS_TMS: R114.2 ; port XDS_TMS
XDS_UART_RX: R136.1 R139.2 TP2.1
XDS_UART_TX: R142.2 R143.2 TP3.1
XDS_UARTB_RS232_RX: R124.2 ; port XDS_UARTB_RS232_RX
XDS_UARTB_RS232_TX: R125.2 ; port XDS_UARTB_RS232_TX
XDSET_1_DM: U18.93(PL7/T1CCP1/USB0DM) ; port XDSET_1_DM
XDSET_1_DP: U18.94(PL6/T1CCP0/USB0DP) ; port XDSET_1_DP
XDSET_1_ID: R160.1 ; port XDSET_1_ID
NetC9_2: C9.2 C10.2 R22.1 U5.1(CATHODE) U18.9(VREFA+)
NetC62_2: C62.2 R135.2 U18.68(VBAT)
NetC65_2: C65.2 U18.88(OSC0) Y1.1(IN/OUT)
NetC66_2: C66.2 U18.89(OSC1) Y1.3(OUT/IN)
NetC69_1: C69.1 R166.1 U18.96(PB1/CAN1TX/I2C5SDA/T4CCP1/U1TX/USB0VBUS)
NetR5_1: R5.1 U18.70(~{RST})
NetR112_1: R112.1 U18.40(PA6/EPI0S8/I2C6SCL/SSI0XDAT2/T3CCP0/U2RX/USB0EPEN)
NetR113_1: R113.1 U18.38(PA5/I2C7SDA/SSI0XDAT1/T2CCP1/U3TX)
NetR114_1: R114.1 U18.36(PA3/I2C8SDA/SSI0FSS/T1CCP1/U4TX)
NetR115_1: R115.1 U18.35(PA2/I2C8SCL/SSI0CLK/T1CCP0/U4RX)
NetR117_2: R117.2 U18.43(PF1/EN0LED2/M0PWM1/SSI3XDAT0/TRD1)
NetR118_2: R118.2 U18.42(PF0/EN0LED0/M0PWM0/SSI3XDAT1/TRD2)
NetR119_1: R119.1 U18.61(PK6/EN0LED1/EPI0S25/I2C4SCL/M0FAULT1)
NetR120_1: R120.1 U18.62(PK5/EN0LED2/EPI0S31/I2C3SDA/M0PWM7)
NetR121_1: R121.1 U18.63(PK4/EN0LED0/EPI0S32/I2C3SCL/M0PWM6)
NetR122_1: R122.1 U18.60(PK7/EPI0S24/I2C4SDA/M0FAULT2/RTCCLK/U0RI)
NetR123_2: R123.2 U18.59(RBIAS)
NetR124_1: R124.1 U18.34(PA1/CAN0TX/I2C9SDA/T0CCP1/U0TX)
NetR125_1: R125.1 U18.33(PA0/CAN0RX/I2C9SCL/T0CCP0/U0RX)
NetR139_1: R139.1 U18.25(PC4/C1-/EPI0S7/U7RX)
NetR142_1: R142.1 U18.24(PC5/C1+/EPI0S6/RTCCLK/U7TX)
NetR160_2: R160.2 U18.95(PB0/CAN1RX/I2C5SCL/T4CCP0/U1RX/USB0ID)

Not connected (* = marked no-connect by the designer): U5 3(NC)*; U18 2(PD1/AIN14/C1O/I2C7SDA/SSI2XDAT0/T0CCP1)* 3(PD2/AIN13/C2O/I2C8SCL/SSI2FSS/T1CCP0)* 4(PD3/AIN12/I2C8SDA/SSI2CLK/T1CCP1)* 5(PQ0/EPI0S20/SSI3CLK)* 6(PQ1/EPI0S21/SSI3FSS)* 11(PQ2/EPI0S22/SSI3XDAT0)* 12(PE3/AIN0/U1DTR)* 13(PE2/AIN1/U1DCD)* 14(PE1/AIN2/U1DSR)* 15(PE0/AIN3/U1RTS)* 18(PK0/AIN16/EPI0S0/U4RX)* 19(PK1/AIN17/EPI0S1/U4TX)* 20(PK2/AIN18/EPI0S2/U4RTS)* 21(PK3/AIN19/EPI0S3/U4CTS)* 22(PC7/C0-/EPI0S4/U5TX)* 23(PC6/C0+/EPI0S5/U5RX)* 27(PQ3/EPI0S23/SSI3XDAT1)* 29(PH0/EPI0S0/U0RTS)* 30(PH1/EPI0S1/U0CTS)* 31(PH2/EPI0S2/U0DCD)* 32(PH3/EPI0S3/U0DSR)* 41(PA7/EPI0S9/I2C6SDA/SSI0XDAT3/T3CCP1/U2TX/USB0EPEN/USB0PFLT)* 44(PF2/M0PWM2/SSI3FSS/TRD0)* 45(PF3/M0PWM3/SSI3CLK/TRCLK)* 46(PF4/EN0LED1/M0FAULT0/SSI3XDAT2/TRD3)* 49(PG0/EN0PPS/EPI0S11/I2C1SCL/M0PWM4)* 50(PG1/EPI0S10/I2C1SDA/M0PWM5)* 53(EN0RXIN)* 54(EN0RXIP)* 56(EN0TXON)* 57(EN0TXOP)* 65(~{HIB})* 67(XOSC1)* 71(PM7/T5CCP1/TMPR0/U0RI)* 72(PM6/T5CCP0/TMPR1/U0DSR)* 73(PM5/T4CCP1/TMPR2/U0DCD)* 74(PM4/T4CCP0/TMPR3/U0CTS)* 75(PM3/EPI0S12/T3CCP1)* 76(PM2/EPI0S13/T3CCP0)* 77(PM1/EPI0S14/T2CCP1)* 78(PM0/EPI0S15/T2CCP0)* 81(PL0/EPI0S16/I2C2SDA/M0FAULT3/USB0D0)* 82(PL1/EPI0S17/I2C2SCL/PHA0/USB0D1)* 83(PL2/C0O/EPI0S18/PHB0/USB0D2)* 84(PL3/C1O/EPI0S19/IDX0/USB0D3)* 85(PL4/EPI0S26/T0CCP0/USB0D4)* 86(PL5/EPI0S33/T0CCP1/USB0D5)* 91(PB2/EPI0S27/I2C0SCL/T5CCP0/USB0STP)* 92(PB3/EPI0S28/I2C0SDA/T5CCP1/USB0CLK)* 97(PC3/SWO/TDO)* 98(PC2/TDI)* 99(PC1/SWDIO/TMS)* 100(PC0/SWCLK/TCK)* 102(PQ4/DIVSCLK/U1RX)* 103(PP2/EPI0S29/U0DTR/USB0NXT)* 104(PP3/EPI0S30/RTCCLK/U0DCD/U1CTS/USB0DIR)* 105(PP4/U0DSR/U3RTS/USB0D7)* 106(PP5/I2C2SCL/U3CTS/USB0D6)* 107(PN0/U1RTS)* 108(PN1/U1CTS)* 109(PN2/EPI0S29/U1DCD/U2RTS)* 110(PN3/EPI0S30/U1DSR/U2CTS)* 116(PJ0/EN0PPS/U3RX)* 117(PJ1/U3TX)* 118(PP0/C2+/SSI3XDAT2/U6RX)* 119(PP1/C2-/SSI3XDAT3/U6TX)* 120(PB5/AIN11/I2C5SDA/SSI1CLK/U0RTS)* 121(PB4/AIN10/I2C5SCL/SSI1FSS/U0CTS)* 123(PE4/AIN9/SSI1XDAT0/U1RI)* 124(PE5/AIN8/SSI1XDAT1)* 125(PD4/AIN7/SSI1XDAT2/T3CCP0/U2RX)* 126(PD5/AIN6/SSI1XDAT3/T3CCP1/U2TX)* 127(PD6/AIN5/SSI2XDAT3/T4CCP0/U2RTS/USB0EPEN)* 128(PD7/AIN4/NMI/SSI2XDAT2/T4CCP1/U2CTS/USB0PFLT)*

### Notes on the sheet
- XDS110
- Design Note: DNP R112 while working on 1V8 I/O domain

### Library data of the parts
C3 C11 C73 = CMP-0006272-2: CAP, CERM, 1 uF, 10 V, +/- 10%, X6S, 0402; Manufacturer: TDK; Polarized: N; Value: 1uF; U/M: EA; Cap_F: 1µF; Value1: Unknown; VDC_V: 16V; TempCo: X5R; TaMin_C: -55°C; TaMax_C: 85°C; Cap_Case: 0402; SizeArea_mm2: 0.5; SizeAreaWB_mm2: 3; SizeX_mm: 1; SizeZ_mm: 0.6; AEC Category: Q200
C9 C67 C70 = CMP-0006352-2: CAP, CERM, 0.01 uF, 25 V, +/- 10%, X7R, 0402; Manufacturer: MuRata; TaMin_C: -55°C; Polarized: N; SizeAreaWB_mm2: 3; Value1: Unknown; U/M: EA; Value: 0.01uF; TaMax_C: 125°C; SizeZ_mm: 0.6; SizeX_mm: 1; SizeY_mm: 0.5; Cap_Case: 0402; Value2: 25V; CompType: Capacitor; Cap_F: 10nF; AEC Category: Q200
C10 C12 C13 C62-C64 C69 C71 = CMP-0078241-1: as C8 on sheet PROC212A_ANALOG_JTAG_MUX, CAN & SOP_CTRL
C14 = CMP-0006302-2: CAP, CERM, 2.2 uF, 10 V, +/- 10%, X7S, 0402; Manufacturer: TDK; TaMin_C: -55°C; ESR_ohm: 5.925m; Polarized: N; SizeAreaWB_mm2: 3; Value1: 0.005925 ohm; U/M: EA; Value: 2.2uF; TaMax_C: 125°C; SizeZ_mm: 0.65; SizeX_mm: 1; SizeY_mm: 0.5; Cap_Case: 0402_065; Value2: 10V; CompType: Capacitor; Cap_F: 2.2µF; IRMS_A: 2.05591A; AEC Category: Q200
C65 C66 = CMP-0860185-1: CAP, CERM, 8 pF, 50 V,+/- 6.25%, C0G/NP0, 0402; Manufacturer: Yageo; Cap_Case: 0402; Polarized: N; TaMax_C: 125°C; SizeY_mm: 0.5; SizeX_mm: 1; Value: 8pF; AEC Category: Q200; U/M: EA; SizeAreaWB_mm2: 3; TaMin_C: -55°C; SizeZ_mm: 0.6
R5 R136 R143 = CMP-0025958-3: as R29 on sheet PROC212A_ANALOG_JTAG_MUX, CAN & SOP_CTRL
R22 R119-R122 = CMP-0026071-3: RES, 1.00 k, 1%, 0.063 W, AEC-Q200 Grade 0, 0402; Manufacturer: Vishay-Dale; Power_W: 63mW; TempCo: 100 ppm/C; Value_Code: 1k00; Value: 1.00k; EIA_Code: E96; Res_ohm: 1k; SizeX_mm: 1; SizeY_mm: 0.5; SizeZ_mm: 0.6; Value2: 0.063W; AEC Qualified: Y; VDC_V: 50V; AEC Category: Q200; AEC Grade: 0
R112-R115 = CMP-0026299-2: RES, 33.2, 1%, 0.063 W, AEC-Q200 Grade 0, 0402; Manufacturer: Vishay-Dale; Power_W: 63mW; TempCo: 100 ppm/C; Value_Code: 33R2; Value: 33.2; EIA_Code: E96; SizeX_mm: 1; SizeY_mm: 0.5; SizeZ_mm: 0.6; Value2: 0.063W; AEC Qualified: Y; AEC Grade: 0; AEC Category: Q200; VDC_V: 50V
R117 R118 R124 R125 R139 R142 R160 = CMP-0002710-1: as R15 on sheet PROC212A_ANALOG_JTAG_MUX, CAN & SOP_CTRL
R123 = CMP-0026413-2: RES, 4.87 k, 1%, 0.063 W, AEC-Q200 Grade 0, 0402; Manufacturer: Vishay-Dale; Power_W: 63mW; TempCo: 100 ppm/C; Value_Code: 4k87; Value: 4.87k; EIA_Code: E96; SizeX_mm: 1; SizeY_mm: 0.5; SizeZ_mm: 0.6; Value2: 0.063W; AEC Qualified: Y; VDC_V: 50V; AEC Category: Q200; AEC Grade: 0
R135 = CMP-0026404-2: RES, 49.9, 1%, 0.063 W, AEC-Q200 Grade 0, 0402; Manufacturer: Vishay-Dale; Power_W: 63mW; TempCo: 100 ppm/C; Value_Code: 49R9; Value: 49.9; EIA_Code: E96; SizeX_mm: 1; SizeY_mm: 0.5; SizeZ_mm: 0.6; Value2: 0.063W; AEC Qualified: Y; VDC_V: 50V; AEC Category: Q200; AEC Grade: 0
R153 R154 = CMP-0078210-2: RES, 330 k, 1%, 0.063 W, AEC-Q200 Grade 0, 0402; Manufacturer: Vishay-Dale; SizeArea_mm2: 0.5; AEC Qualified: Y; AEC Category: Q200; Value: 330k; SizeZ_mm: 0.6; TempCo: 100 ppm/C; AEC Grade: 0; Power_W: 63mW; VDC_V: 50V; Value2: 0.063W; SizeX_mm: 1
R166 = CMP-0026993-2: RES, 100, 5%, 0.1 W, AEC-Q200 Grade 0, 0402; Manufacturer: Panasonic; Power_W: 100mW; TempCo: 200 ppm/C; Value_Code: 100R; U/M: EA; Value: 100; EIA_Code: E24; SizeX_mm: 1; SizeY_mm: 0.5; SizeZ_mm: 0.6; Value2: 0.1W; AEC Qualified: Y; AEC Grade: 0; AEC Category: Q200
R184 R186 = CMP-0026992-3: RES, 0, 5%, 0.1 W, AEC-Q200 Grade 0, 0402; Manufacturer: Panasonic; Power_W: 100mW; TempCo: 600 ppm/C; Value_Code: 0000; Value: 0; EIA_Code: E24; SizeX_mm: 1; SizeY_mm: 0.5; SizeZ_mm: 0.6; Value2: 0.1W; AEC Qualified: Y; VDC_V: 50V; AEC Category: Q200; SizeAreaWB_mm2: 3
S3 = CMP-0002230-1: Switch, SPST, 2 Pos, 25mA, 24VDC, SMD; Manufacturer: CTS Electrocomponents; CurrentRating_mA: 25A; PositionCount: 2; VDC_V: 24V; SwitchFunction: Off-On
TP2 TP3 = CMP-0078143-3: TEST POINT.  No entry in BOM.
U5 = CMP-0033001-1: Precision Micropower Shunt Voltage Reference, 0.5% accuracy, 2.5 V, 15 ppm / degC, 15 mA, -40 to 125 degC, 3-pin SOT-23 (DBZ), Green (RoHS & no Sb/Br); Manufacturer: Texas Instruments; Initial Accuracy @ 25/deg C(%): 0.5; Temp Coeff(Typ)(ppm/ degree C): 15; Temp Coeff(Max)(ppm/ degree C): 100; Rating: Catalog; Min Iz for Regulation(uA): 75; VO(V): 2.5
U18 = CMP-0029856-2: Tiva C Series Microcontroller, 1024 KB Flash, 256 KB SRAM, 12 Bit, 20 Channels, -40 to 105 degC, 128-Pin TQFP (PDT), Green (RoHS & no Sb/Br), Tray; Manufacturer: Texas Instruments; ADC Channels: 20; CPU: ARM Cortex-M4; Flash: 1024 KB; ADC Resolution: 12 Bits; Max Speed: 120 MHz; SRAM: 256 KB; SizeAreaWB_mm2: 324.0; SizeArea_mm2: 256.0; SizeX_mm: 16.0; SizeZ_mm: 1.2; CompType: IC
Y1 = CMP-0095014-1: 16 MHz ±15ppm Crystal 8pF 80 Ohms 4-SMD, No Lead; Manufacturer: ECS; Frequency Stability: 50ppm; SizeZ_mm: 0.8mm; Frequency_Fixed: 16MHz; AEC Qualified: Yes; Esr: 80; AEC Grade: Grade 1

## Sheet PROC212A_FTDI.SchDoc: FTDI_USB to SPI/I2C/UART converter
size 431 x 279 mm; Date: Not shown in title block; ApprovedBy: Not shown in title block; CheckedBy: Not shown in title block; Author: Not shown in title block; CompanyName: Not shown in title block; DrawnBy: Mistral; Engineer: Not shown in title block; Organization: Not shown in title block; Address1: Not shown in title block; Address2: Not shown in title block; Address3: Not shown in title block; Address4: Not shown in title block; DocumentNumber: 12; Revision: Use project parameter SCH_Rev; SheetNumber: 12; SheetTotal: 15; PageSetup: Record=PageOptions¦CenterHorizontal=True¦CenterVertical=True¦PrintScale=1.00¦XCorrection=1.00¦YCorrection=1.00¦PrintKind=0¦BorderSize=5000000¦LeftOffset=0¦BottomOffset=0¦Orientation=2¦PaperLength=1000¦PaperWidth=1000¦Scale=100¦PaperSource=15¦PrintQuality=600¦MediaType=1¦DitherType=10¦PaperKind=Letter¦PrintScaleMode=1
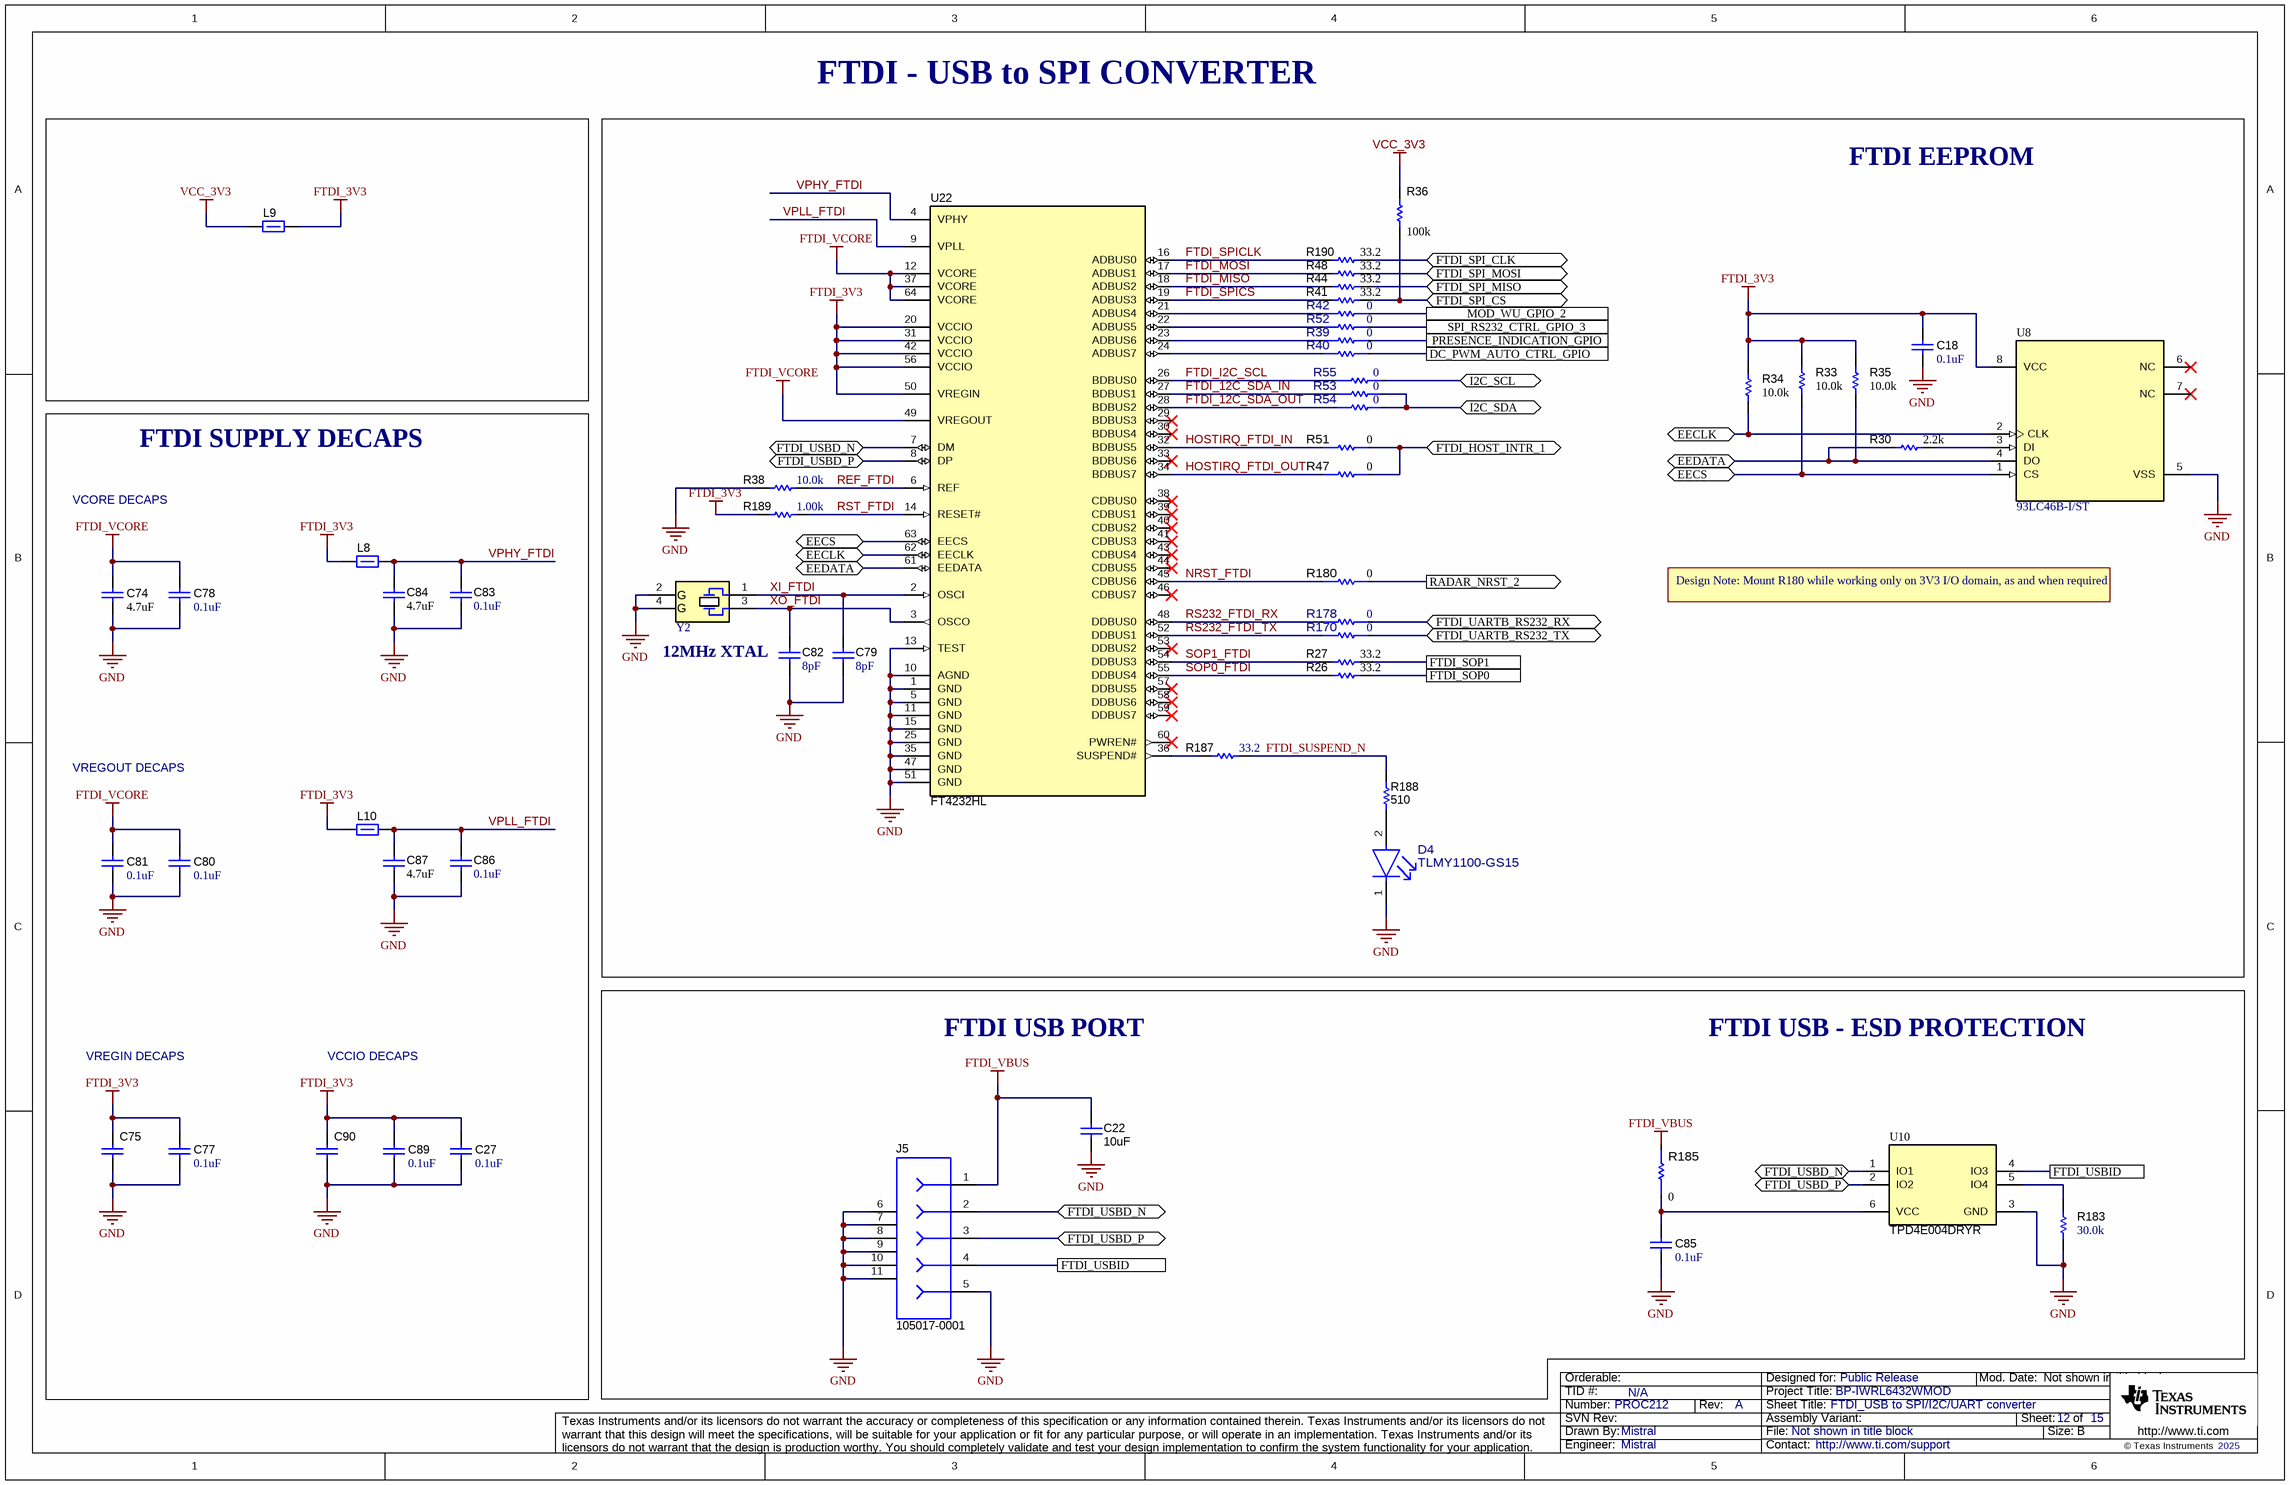
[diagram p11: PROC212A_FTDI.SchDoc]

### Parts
C18  ValueDisplayed: 0.1uF  [0402]  (hidden comment: GCM155R71H104KE02D)
C22  ValueDisplayed: 10uF  [0603S]  (hidden comment: GRT188R61A106KE13D)
C27  ValueDisplayed: 0.1uF  [0402]  (hidden comment: GCM155R71H104KE02D)
C74  ValueDisplayed: 4.7uF  [0603L]  (hidden comment: C1608X7S1A475K080AC)
C75  CL10B105KA8NNNC  [0603]  (value not drawn)
C77  ValueDisplayed: 0.1uF  [0402]  (hidden comment: GCM155R71H104KE02D)
C78  ValueDisplayed: 0.1uF  [0402]  (hidden comment: GCM155R71H104KE02D)
C79  Cap_F: 8pF  [0402L]  (hidden comment: GCM1555C1H8R0DA16D)
C80  ValueDisplayed: 0.1uF  [0402]  (hidden comment: GCM155R71H104KE02D)
C81  ValueDisplayed: 0.1uF  [0402]  (hidden comment: GCM155R71H104KE02D)
C82  Cap_F: 8pF  [0402L]  (hidden comment: GCM1555C1H8R0DA16D)
C83  ValueDisplayed: 0.1uF  [0402]  (hidden comment: GCM155R71H104KE02D)
C84  ValueDisplayed: 4.7uF  [0603L]  (hidden comment: C1608X7S1A475K080AC)
C85  ValueDisplayed: 0.1uF  [0402]  (hidden comment: GCM155R71H104KE02D)
C86  ValueDisplayed: 0.1uF  [0402]  (hidden comment: GCM155R71H104KE02D)
C87  ValueDisplayed: 4.7uF  [0603L]  (hidden comment: C1608X7S1A475K080AC)
C89  ValueDisplayed: 0.1uF  [0402]  (hidden comment: GCM155R71H104KE02D)
C90  CL10B105KA8NNNC  [0603]  (value not drawn)
D4  TLMY1100-GS15  [FP-TLMY1100-GS15_0603-MFG]
J5  105017-0001  [CONN_105017-0001]
L8  BLM15HG601SN1D  [0402L]  (value not drawn)
L9  BLM15HG601SN1D  [0402L]  (value not drawn)
L10  BLM15HG601SN1D  [0402L]  (value not drawn)
R26  ValueDisplayed: 33.2  [0402]  (hidden comment: CRCW040233R2FKED)
R27  ValueDisplayed: 33.2  [0402]  (hidden comment: CRCW040233R2FKED)
R30  ValueDisplayed: 2.2k  [0402L]  (hidden comment: CRCW04022K20JNED)
R33  ValueDisplayed: 10.0k  [0402L]  (hidden comment: CRCW040210K0FKED)
R34  ValueDisplayed: 10.0k  [0402L]  (hidden comment: CRCW040210K0FKED)
R35  ValueDisplayed: 10.0k  [0402L]  (hidden comment: CRCW040210K0FKED)
R36  ValueDisplayed: 100k  [0402]  (hidden comment: CRCW0402100KFKED)
R38  ValueDisplayed: 10.0k  [0402L]  (hidden comment: CRCW040210K0FKED)
R39  value 0  [FP-ERJ-2GE0R00X_0402-MFG]  (hidden comment: ERJ-2GE0R00X)
R40  value 0  [FP-ERJ-2GE0R00X_0402-MFG]  (hidden comment: ERJ-2GE0R00X)
R41  ValueDisplayed: 33.2  [0402]  (hidden comment: CRCW040233R2FKED)
R42  value 0  [FP-ERJ-2GE0R00X_0402-MFG]  (hidden comment: ERJ-2GE0R00X)
R44  ValueDisplayed: 33.2  [0402]  (hidden comment: CRCW040233R2FKED)
R47  value 0  [FP-ERJ-2GE0R00X_0402-MFG]  (hidden comment: ERJ-2GE0R00X)
R48  ValueDisplayed: 33.2  [0402]  (hidden comment: CRCW040233R2FKED)
R51  value 0  [FP-ERJ-2GE0R00X_0402-MFG]  (hidden comment: ERJ-2GE0R00X)
R52  value 0  [FP-ERJ-2GE0R00X_0402-MFG]  (hidden comment: ERJ-2GE0R00X)
R53  value 0  [FP-ERJ-2GE0R00X_0402-MFG]  (hidden comment: ERJ-2GE0R00X)
R54  value 0  [FP-ERJ-2GE0R00X_0402-MFG]  (hidden comment: ERJ-2GE0R00X)
R55  value 0  [FP-ERJ-2GE0R00X_0402-MFG]  (hidden comment: ERJ-2GE0R00X)
R170  value 0  [FP-ERJ-2GE0R00X_0402-MFG]  (hidden comment: ERJ-2GE0R00X)
R178  value 0  [FP-ERJ-2GE0R00X_0402-MFG]  (hidden comment: ERJ-2GE0R00X)
R180  value 0  [FP-ERJ-2GE0R00X_0402-MFG]  (hidden comment: ERJ-2GE0R00X)
R183  ValueDisplayed: 30.0k  [0402L]  (hidden comment: CRCW040230K0FKED)
R185  value 0  [FP-ERJ-2GE0R00X_0402-MFG]  (hidden comment: ERJ-2GE0R00X)
R187  ValueDisplayed: 33.2  [0402]  (hidden comment: CRCW040233R2FKED)
R188  ValueDisplayed: 510  [0402L]  (hidden comment: ERJ-2GEJ511X)
R189  ValueDisplayed: 1.00k  [0402]  (hidden comment: ERJ-2RKF1001X)
R190  ValueDisplayed: 33.2  [0402]  (hidden comment: CRCW040233R2FKED)
U8  93LC46B-I/ST  [TSSOP-8]
U10  TPD4E004DRYR  [DRY0006A]
U22  FT4232HL  [LQFP64_N]
Y2  NX3225SA-12.000M-STD-CRS-2  [NDK_NX3225SA]  (value not drawn)

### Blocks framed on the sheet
FTDI EEPROM: C18 C79 C82 D4 R26 R27 R30 R33-R36 R38-R42 R44 R47 R48 R51-R55 R170 R178 R180 R187-R190 U8 U22 Y2
FTDI SUPPLY DECAPS: C27 C74 C75 C77 C78 C80 C81 C83 C84 C86 C87 C89 C90 L8 L10

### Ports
DC_PWM_AUTO_CTRL_GPIO, EECLK (bidir), EECS (bidir), EEDATA (bidir), FTDI_HOST_INTR_1 (bidir), FTDI_SOP0, FTDI_SOP1, FTDI_SPI_CLK (bidir), FTDI_SPI_CS (bidir), FTDI_SPI_MISO (bidir), FTDI_SPI_MOSI (bidir), FTDI_UARTB_RS232_RX (bidir), FTDI_UARTB_RS232_TX (bidir), FTDI_USBD_N (bidir), FTDI_USBD_P (bidir), FTDI_USBID, I2C_SCL (bidir), I2C_SDA (bidir), MOD_WU_GPIO_2, PRESENCE_INDICATION_GPIO, RADAR_NRST_2 (out), SPI_RS232_CTRL_GPIO_3

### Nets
FTDI_3V3: C18.1 C27.1 C75.2 C77.1 C89.1 C90.2 L8.1 L9.2 L10.1 R33.2 R34.2 R35.2 R189.1 U8.8(VCC) U22.20(VCCIO) U22.31(VCCIO) U22.42(VCCIO) U22.50(VREGIN) U22.56(VCCIO)
FTDI_VBUS: C22.2 J5.1 R185.2
FTDI_VCORE: C74.1 C78.1 C80.1 C81.1 U22.12(VCORE) U22.37(VCORE) U22.49(VREGOUT) U22.64(VCORE)
GND: C18.2 C22.1 C27.2 C74.2 C75.1 C77.2 C78.2 C79.2 C80.2 C81.2 C82.2 C83.1 C84.2 C85.2 C86.1 C87.2 C89.2 C90.1 D4.1(C) J5.5 J5.6 J5.7 J5.8 J5.9 J5.10 J5.11 R38.1 R183.1 U8.5(VSS) U10.3(GND) U22.1(GND) U22.5(GND) U22.10(AGND) U22.11(GND) U22.13(TEST) U22.15(GND) U22.25(GND) U22.35(GND) U22.47(GND) U22.51(GND) Y2.2(GND) Y2.4(GND)
VCC_3V3: L9.1 R36.2
DC_PWM_AUTO_CTRL_GPIO: R40.2 ; port DC_PWM_AUTO_CTRL_GPIO
EECLK: R34.1 U8.2(CLK) U22.62(EECLK) ; port EECLK
EECS: R33.1 U8.1(CS) U22.63(EECS) ; port EECS
EEDATA: R30.1 R35.1 U8.4(DO) U22.61(EEDATA) ; port EEDATA
FTDI_12C_SDA_IN: R53.1 U22.27(BDBUS1)
FTDI_12C_SDA_OUT: R54.1 U22.28(BDBUS2)
FTDI_HOST_INTR_1: R47.2 R51.2 ; port FTDI_HOST_INTR_1
FTDI_I2C_SCL: R55.1 U22.26(BDBUS0)
FTDI_MISO: R44.1 U22.18(ADBUS2)
FTDI_MOSI: R48.1 U22.17(ADBUS1)
FTDI_SOP0: R26.2 ; port FTDI_SOP0
FTDI_SOP1: R27.2 ; port FTDI_SOP1
FTDI_SPI_CLK: R190.2 ; port FTDI_SPI_CLK
FTDI_SPI_CS: R36.1 R41.2 ; port FTDI_SPI_CS
FTDI_SPI_MISO: R44.2 ; port FTDI_SPI_MISO
FTDI_SPI_MOSI: R48.2 ; port FTDI_SPI_MOSI
FTDI_SPICLK: R190.1 U22.16(ADBUS0)
FTDI_SPICS: R41.1 U22.19(ADBUS3)
FTDI_SUSPEND_N: R187.2 R188.1
FTDI_UARTB_RS232_RX: R178.2 ; port FTDI_UARTB_RS232_RX
FTDI_UARTB_RS232_TX: R170.2 ; port FTDI_UARTB_RS232_TX
FTDI_USBD_N: J5.2 U10.1(IO1) U22.7(DM) ; port FTDI_USBD_N
FTDI_USBD_P: J5.3 U10.2(IO2) U22.8(DP) ; port FTDI_USBD_P
FTDI_USBID: J5.4 U10.4(IO3) ; port FTDI_USBID
HOSTIRQ_FTDI_IN: R51.1 U22.32(BDBUS5)
HOSTIRQ_FTDI_OUT: R47.1 U22.34(BDBUS7)
I2C_SCL: R55.2 ; port I2C_SCL
I2C_SDA: R53.2 R54.2 ; port I2C_SDA
MOD_WU_GPIO_2: R42.2 ; port MOD_WU_GPIO_2
NRST_FTDI: R180.1 U22.45(CDBUS6)
PRESENCE_INDICATION_GPIO: R39.2 ; port PRESENCE_INDICATION_GPIO
RADAR_NRST_2: R180.2 ; port RADAR_NRST_2
REF_FTDI: R38.2 U22.6(REF)
RS232_FTDI_RX: R178.1 U22.48(DDBUS0)
RS232_FTDI_TX: R170.1 U22.52(DDBUS1)
RST_FTDI: R189.2 U22.14(RESET#)
SOP0_FTDI: R26.1 U22.55(DDBUS4)
SOP1_FTDI: R27.1 U22.54(DDBUS3)
SPI_RS232_CTRL_GPIO_3: R52.2 ; port SPI_RS232_CTRL_GPIO_3
VPHY_FTDI: C83.2 C84.1 L8.2 U22.4(VPHY)
VPLL_FTDI: C86.2 C87.1 L10.2 U22.9(VPLL)
XI_FTDI: C79.1 U22.2(OSCI) Y2.1
XO_FTDI: C82.1 U22.3(OSCO) Y2.3
NetC85_1: C85.1 R185.1 U10.6(VCC)
NetD4_2: D4.2(A) R188.2
NetR30_2: R30.2 U8.3(DI)
NetR39_1: R39.1 U22.23(ADBUS6)
NetR40_1: R40.1 U22.24(ADBUS7)
NetR42_1: R42.1 U22.21(ADBUS4)
NetR52_1: R52.1 U22.22(ADBUS5)
NetR183_2: R183.2 U10.5(IO4)
NetR187_1: R187.1 U22.36(SUSPEND#)

Not connected (* = marked no-connect by the designer): U8 6(NC)* 7(NC)*; U22 29(BDBUS3)* 30(BDBUS4)* 33(BDBUS6)* 38(CDBUS0)* 39(CDBUS1)* 40(CDBUS2)* 41(CDBUS3)* 43(CDBUS4)* 44(CDBUS5)* 46(CDBUS7)* 53(DDBUS2)* 57(DDBUS5)* 58(DDBUS6)* 59(DDBUS7)* 60(PWREN#)*

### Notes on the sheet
- FTDI - USB to SPI CONVERTER
- VCORE DECAPS
- Design Note: Mount R180 while working only on 3V3 I/O domain, as and when required
- 12MHz XTAL
- VREGOUT DECAPS
- VREGIN DECAPS
- VCCIO DECAPS
- FTDI USB PORT
- FTDI USB - ESD PROTECTION

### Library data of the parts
C18 C27 C77 C78 C80 C81 C83 C85 C86 C89 = CMP-0006356-2: as C15 on sheet PROC212A_ANALOG_JTAG_MUX, CAN & SOP_CTRL
C22 = CMP-0007497-5: CAP, CERM, 10 uF, 10 V, +/- 10%, X5R, 0603; Manufacturer: MuRata; Polarized: N; Value: 10uF; U/M: EA; Cap_F: 10µF; Tolerance_%: 20%; Value1: Unknown; VDC_V: 10V; TempCo: X7R; TaMin_C: -55°C; TaMax_C: 125°C; Cap_Case: 0603; SizeArea_mm2: 1.28; SizeAreaWB_mm2: 4.68; SizeX_mm: 1.6; SizeY_mm: 0.8; SizeZ_mm: 1; AEC Category: Q200
C74 C84 C87 = CMP-0007058-4: CAP, CERM, 4.7 uF, 10 V, +/- 10%, X7S, 0603; Manufacturer: TDK; TaMin_C: -55°C; Polarized: N; SizeAreaWB_mm2: 4.68; Value1: Unknown; U/M: EA; Value: 4.7uF; TaMax_C: 125°C; SizeZ_mm: 1; SizeX_mm: 1.6; SizeY_mm: 0.8; Cap_Case: 0603; Value2: 10V; SizeArea_mm2: 1.28; CompType: Capacitor; Cap_F: 4.7µF; AEC Category: Q200
C75 C90 = CMP-0086540-3: CAP, 1uF, 25V, ±10%, X7R, 0603; Manufacturer: Samsung; TempCo: 15%; SizeZ_mm: 0.9mm; AEC Qualified: No; Cap_F: 1µF; Symbol Name: SYM-CL10B105KA8NNNC
C79 C82 = CMP-0087060-3: Cap Ceramic 8pF 50V C0G 0.5pF SMD 0402 125C Paper T/R; Manufacturer: Murata Electronics North America; AEC Qualified: Yes; TempCo: 30ppm/°C; AEC Grade: Grade 1; SizeZ_mm: 0.55mm
D4 = CMP-0121062-1: Yellow 589nm LED Indication - Discrete 2.1V 0603 (1608 Metric); Manufacturer: Vishay; Angle: 160°; LambdaP: 591nm; Power_TotalModule: 90mW; SizeZ_mm: 0.65mm; Tjmax_C: 120°C; Vr_V: 12V; AEC Grade: Grade 3; AEC Qualified: Yes; Forward Current: 20mA; Led Orientation: Top View; Luminous Intensity: 80mcd; TaMax_C: +100°C; TaMin_C: -40°C
J5 = CMP-0055293-1: Connector, Receptacle, Micro-USB Type B, R/A, Bottom Mount SMT; Manufacturer: Molex; CNHeader: FALSE; Green_Lifecycle: Active; Gender: Female; Green_REACh: Passed; CompType: USB; CT: TRUE
L8-L10 = CMP-0081523-1: Ferrite Bead, 600 ohm @ 100 MHz, 0.3 A, 0402; Manufacturer: MuRata; SizeAreaWB_mm2: 3; SizeArea_mm2: 0.5; Value: 600 ohm; SizeZ_mm: 0.6; Imax_A: 3dA; ZTyp@100MHz_Ohm: 600; Value2: 0.3A; Value1: 0.7 ohm; DCR_ohm: 7d; SizeX_mm: 1; Ztyp@1GHz_Ohm: 1k
R26 R27 R41 R44 R48 R187 R190 = CMP-0026299-2: RES, 33.2, 1%, 0.063 W, AEC-Q200 Grade 0, 0402; Manufacturer: Vishay-Dale; Power_W: 63mW; TempCo: 100 ppm/C; Value_Code: 33R2; Value: 33.2; EIA_Code: E96; SizeX_mm: 1; SizeY_mm: 0.5; SizeZ_mm: 0.6; Value2: 0.063W; AEC Qualified: Y; VDC_V: 50V; AEC Category: Q200; AEC Grade: 0
R30 = CMP-0026890-5: RES, 2.2 k, 5%, 0.063 W, AEC-Q200 Grade 0, 0402; Manufacturer: Vishay-Dale; Power_W: 63mW; TempCo: 200 ppm/C; Value_Code: 2k20; Value: 2.2k; EIA_Code: E24; SizeX_mm: 1; SizeY_mm: 0.5; SizeZ_mm: 0.6; Value2: 0.063W; AEC Qualified: Y; VDC_V: 50V; AEC Category: Q200; AEC Grade: 0
R33-R35 R38 = CMP-0025958-3: as R29 on sheet PROC212A_ANALOG_JTAG_MUX, CAN & SOP_CTRL
R36 = CMP-0025950-3: RES, 100 k, 1%, 0.063 W, AEC-Q200 Grade 0, 0402; Manufacturer: Vishay-Dale; Power_W: 63mW; TempCo: 100 ppm/C; Value: 100k; EIA_Code: E96; SizeX_mm: 1; SizeY_mm: 0.5; SizeZ_mm: 0.6; Value2: 0.063W; AEC Qualified: Y; VDC_V: 50V; AEC Category: Q200; AEC Grade: 0
R39 R40 R42 R47 R51-R55 R170 R178 R180 R185 = CMP-0002710-1: as R15 on sheet PROC212A_ANALOG_JTAG_MUX, CAN & SOP_CTRL
R183 = CMP-0078244-2: RES, 30.0 k, 1%, 0.063 W, AEC-Q200 Grade 0, 0402; Manufacturer: Vishay-Dale; Power_W: 63mW; Green_Lifecycle: Active; TempCo: 100 ppm/C; Value_Code: 30k0; Green_REACh: Passed; Value: 30.0k; Res_ohm: 30k; SizeX_mm: 1; SizeY_mm: 0.5; SizeZ_mm: 0.6; Value2: 0.063W; AEC Qualified: Y; VDC_V: 50V; AEC Grade: 0; AEC Category: Q200
R188 = CMP-0078212-1: RES, 510, 5%, 0.1 W, AEC-Q200 Grade 0, 0402; Manufacturer: Panasonic; Value_Code: 510R; SizeArea_mm2: 0.5; AEC Qualified: Y; AEC Category: Q200; Value: 510; SizeZ_mm: 0.6; EIA_Code: E24; TempCo: 200 ppm/C; AEC Grade: 0; Power_W: 100mW; VDC_V: 50V; Value2: 0.1W; U/M: EA; SizeX_mm: 1
R189 = CMP-0026657-1: RES, 1.00 k, 1%, 0.1 W, 0402; Manufacturer: Panasonic; Power_W: 100mW; TempCo: 100 ppm/C; Value_Code: 1k00; Value: 1.00k; EIA_Code: E96; Res_ohm: 1k; SizeX_mm: 1; SizeY_mm: 0.5; SizeZ_mm: 0.6; Value2: 0.1W; VDC_V: 50V; AEC Category: Q200; U/M: EA
U8 = CMP-0081524-1: 1K Microwire Compatible Serial EEPROM, TSSOP-8; Manufacturer: Microchip; SizeArea_mm2: 19.2; SizeAreaWB_mm2: 42; SizeY_mm: 3; SizeZ_mm: 1.2; SizeX_mm: 6.4
U10 = CMP-0043115-3: 4-Channel ESD Protection Array for High-Speed Data Interfaces, DRY0006A (USON-6); Manufacturer: Texas Instruments; IO Leakage Current(nA): 1; USB High Speed: TRUE; IO Capacitance(Typ)(pF): 1.6; Eco-Plan: Green (RoHS & no Sb/Br); IEC 61000-4-2 Contact(+/- kV): 8; Breakdown Voltage(Min)(V): 6; IEC 61000-4-2 Air-Gap(+/- kV): 12; AEC Category: Q200; AEC Qualified: N; CompType: IC; SizeAreaWB_mm2: 4.9; SizeArea_mm2: 1.45; SizeX_mm: 1.0; SizeZ_mm: 0.6; Rating: Catalog
U22 = CMP-0004747-1: Quad High Speed USB to Multipurpose UART/MPSSE IC; Manufacturer: FTDI
Y2 = CMP-0081529-1: Crystal, 12 MHz, 15 ppm, 8 pF, AEC-Q200 Grade 1, SMD; Manufacturer: NDK; TaMin_C: -40°C; Frequency Tolerance: 15 ppm; Frequency Stability: 50 ppm; Load Capacitance: 8 pF; Frequency_Fixed: 12MHz; TaMax_C: 125°C; AEC Qualified: Y; AEC Grade: 1; AEC Category: Q200

## Sheet PROC212A_Reset_SW_LED_&_PRESENCE_LED.SchDoc: RESET SWITCH & LED, PRESENCE LED
size 431 x 279 mm; Date: Not shown in title block; ApprovedBy: Not shown in title block; CheckedBy: Not shown in title block; Author: Not shown in title block; CompanyName: Not shown in title block; DrawnBy: Mistral; Engineer: Not shown in title block; Organization: Not shown in title block; Address1: Not shown in title block; Address2: Not shown in title block; Address3: Not shown in title block; Address4: Not shown in title block; DocumentNumber: 13; Revision: Use project parameter SCH_Rev; SheetNumber: 13; SheetTotal: 15; PageSetup: Record=PageOptions¦CenterHorizontal=True¦CenterVertical=True¦PrintScale=1.00¦XCorrection=1.00¦YCorrection=1.00¦PrintKind=0¦BorderSize=5000000¦LeftOffset=0¦BottomOffset=0¦Orientation=2¦PaperLength=1000¦PaperWidth=1000¦Scale=100¦PaperSource=15¦PrintQuality=600¦MediaType=1¦DitherType=10¦PaperKind=Letter¦PrintScaleMode=1
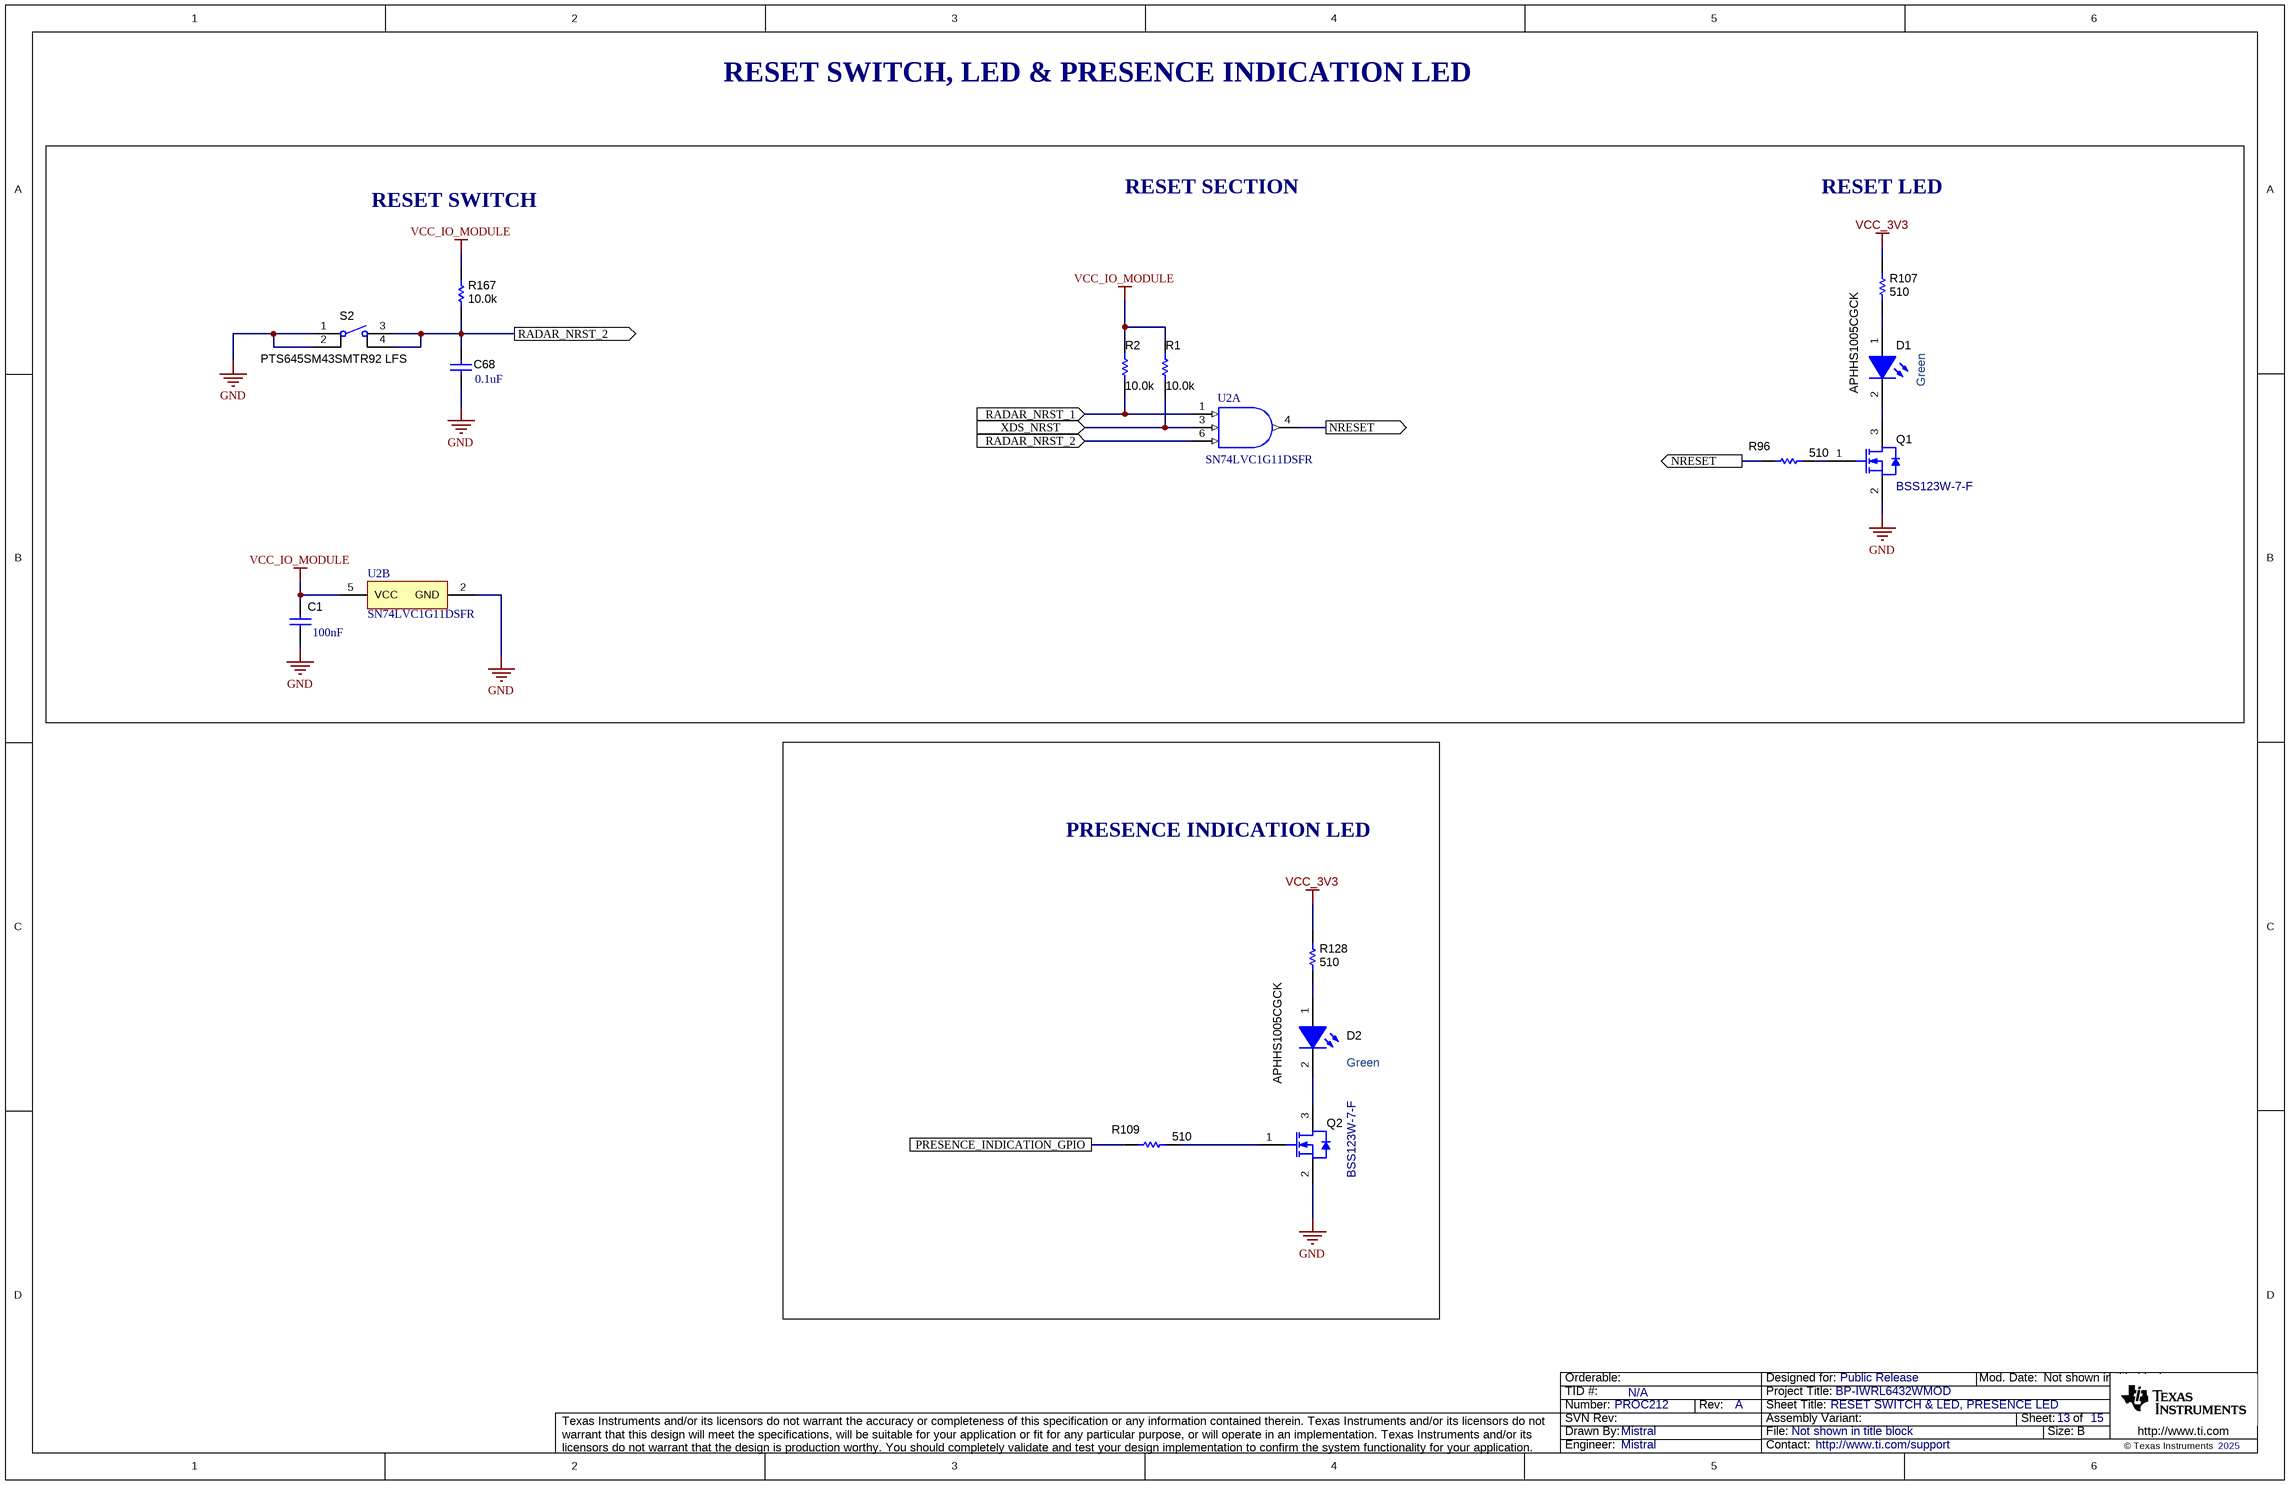
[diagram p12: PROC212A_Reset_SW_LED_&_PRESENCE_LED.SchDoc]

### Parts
C1  Cap_F: 100nF  [0402]  (hidden comment: GCM155R71H104KE02D)
C68  ValueDisplayed: 0.1uF  [0402]  (hidden comment: GCM155R71H104KE02D)
D1  APHHS1005CGCK  Color: Green  [APHHS1005_Green]
D2  APHHS1005CGCK  Color: Green  [APHHS1005_Green]
Q1  BSS123W-7-F  [SOT-323]
Q2  BSS123W-7-F  [SOT-323]
R1  ValueDisplayed: 10.0k  [0402L]  (hidden comment: CRCW040210K0FKED)
R2  ValueDisplayed: 10.0k  [0402L]  (hidden comment: CRCW040210K0FKED)
R96  ValueDisplayed: 510  [0402L]  (hidden comment: ERJ-2GEJ511X)
R107  ValueDisplayed: 510  [0402L]  (hidden comment: ERJ-2GEJ511X)
R109  ValueDisplayed: 510  [0402L]  (hidden comment: ERJ-2GEJ511X)
R128  ValueDisplayed: 510  [0402L]  (hidden comment: ERJ-2GEJ511X)
R167  ValueDisplayed: 10.0k  [0402L]  (hidden comment: CRCW040210K0FKED)
S2  PTS645SM43SMTR92 LFS  [SW_PTS645SM43SMT]
U2  SN74LVC1G11DSFR  [DSF0006A]  (parts A,B of 2)

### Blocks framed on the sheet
PRESENCE INDICATION LED: D2 Q2 R109 R128

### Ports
NRESET (out), PRESENCE_INDICATION_GPIO, RADAR_NRST_1 (in), RADAR_NRST_2 (in), RADAR_NRST_2 (out), XDS_NRST (in)

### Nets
GND: C1.1 C68.2 Q1.2(S) Q2.2(S) S2.1 S2.2 U2.2(GND)
VCC_3V3: R107.2 R128.2
VCC_IO_MODULE: C1.2 R1.2 R2.2 R167.2 U2.5(VCC)
NRESET: R96.2 U2.4(Y) ; port NRESET
PRESENCE_INDICATION_GPIO: R109.2 ; port PRESENCE_INDICATION_GPIO
RADAR_NRST_1: R2.1 U2.1(A) ; port RADAR_NRST_1
RADAR_NRST_2: C68.1 R167.1 S2.3 S2.4 U2.6(C) ; port RADAR_NRST_2
XDS_NRST: R1.1 U2.3(B) ; port XDS_NRST
NetD1_1: D1.1(A) R107.1
NetD1_2: D1.2(K) Q1.3(D)
NetD2_1: D2.1(A) R128.1
NetD2_2: D2.2(K) Q2.3(D)
NetQ1_1: Q1.1(G) R96.1
NetQ2_1: Q2.1(G) R109.1

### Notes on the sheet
- RESET SWITCH, LED & PRESENCE INDICATION LED
- RESET SWITCH
- RESET SECTION
- RESET LED

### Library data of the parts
C1 = CMP-0006356-2: CAP, CERM, 0.1 uF, 50 V, +/- 10%, X7R, AEC-Q200 Grade 1, 0402; Manufacturer: MuRata; AEC Qualified: Y; SizeZ_mm: 0.6; VDC_V: 50V; AEC Category: Q200; AEC Grade: 1; Polarized: N; SizeArea_mm2: 0.5; SizeAreaWB_mm2: 3; TaMax_C: 125°C; TaMin_C: -55°C; U/M: EA; Value1: Unknown; Value: 0.1uF
C68 = CMP-0006356-2: as C2 on sheet PROC212A_Current_sensors_EPROM
D1 D2 = CMP-0067682-2: LED, Green, SMD; Manufacturer: Kingbright; Angle: 120.0; Power_TotalModule: 75mW; SizeZ_mm: 0.6; Vf_V: 2.1V; Vr_V: 5V; Io_A: 20mA; Ir_A: 10µA; SizeArea_mm2: 0.5; SizeAreaWB_mm2: 3.0; SizeX_mm: 1.0; Tjmax_C: 85°C; Value1: 0.075W
Q1 Q2 = CMP-0000948-2: MOSFET, N-CH, 100 V, 0.17 A, SOT-323; Alternate Manufacturer: None; Manufacturer: Diodes Inc.; SizeZ_mm: 1.1; ChType: N; Value1: 1; VdsMax_V: 100V; SizeX_mm: 2.2; Vgs_V: 20V; Value: 100V; Rdson45_ohm: 10; SizeArea_mm2: 4.84; AEC Category: Q101; IdsMax_A: 1.7dA; SizeAreaWB_mm2: 10.24; U/M: EA
R1 R2 R167 = CMP-0025958-3: as R29 on sheet PROC212A_ANALOG_JTAG_MUX, CAN & SOP_CTRL
R96 R107 R109 R128 = CMP-0078212-1: as R188 on sheet PROC212A_FTDI
S2 = CMP-0079642-1: Switch, SPST-NO, Off-Mom, 0.05 A, 12 VDC, SMD; Manufacturer: C&K Components; SizeAreaWB_mm2: 88; SizeArea_mm2: 54; SizeZ_mm: 4.4; SizeY_mm: 6; VDC_V: 12V; CurrentRating_mA: 50A; PositionCount: 1; SizeX_mm: 9
U2 = CMP-0051215-4: Single 3-Input Positive-AND Gate, DSF0006A, LARGE T&R; Manufacturer: Texas Instruments; Output Type: CMOS; Bits(#): 1; Input Type: CMOS/TTL; Technology Family: LVC; Schmitt Trigger: No; VCC(Max)(V): 5.5; Gate Type: AND; Rating: Catalog; Output Drive (IOL/IOH)(Max)(mA): 32/-32; ICC @ Nom Voltage(Max)(mA): 0.01; VCC(Min)(V): 1.65; F @ Nom Voltage(Max)(Mhz): 150; Logic: True; Voltage(Nom)(V): 1.8,2.5,3.3,5; tpd @ Nom Voltage(Max)(ns): 20,7.8,6.2,4.6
